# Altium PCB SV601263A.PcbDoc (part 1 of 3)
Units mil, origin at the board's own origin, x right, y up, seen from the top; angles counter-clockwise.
Board outline 4070 x 6530 mil, 6 copper layers (Top Layer, Signal Layer 1, Signal Layer 2, Signal Layer 3, Signal Layer 4, Bottom Layer), stack 60.36 mil thick; 305 components, 177 nets, 942 pads, 354 vias.
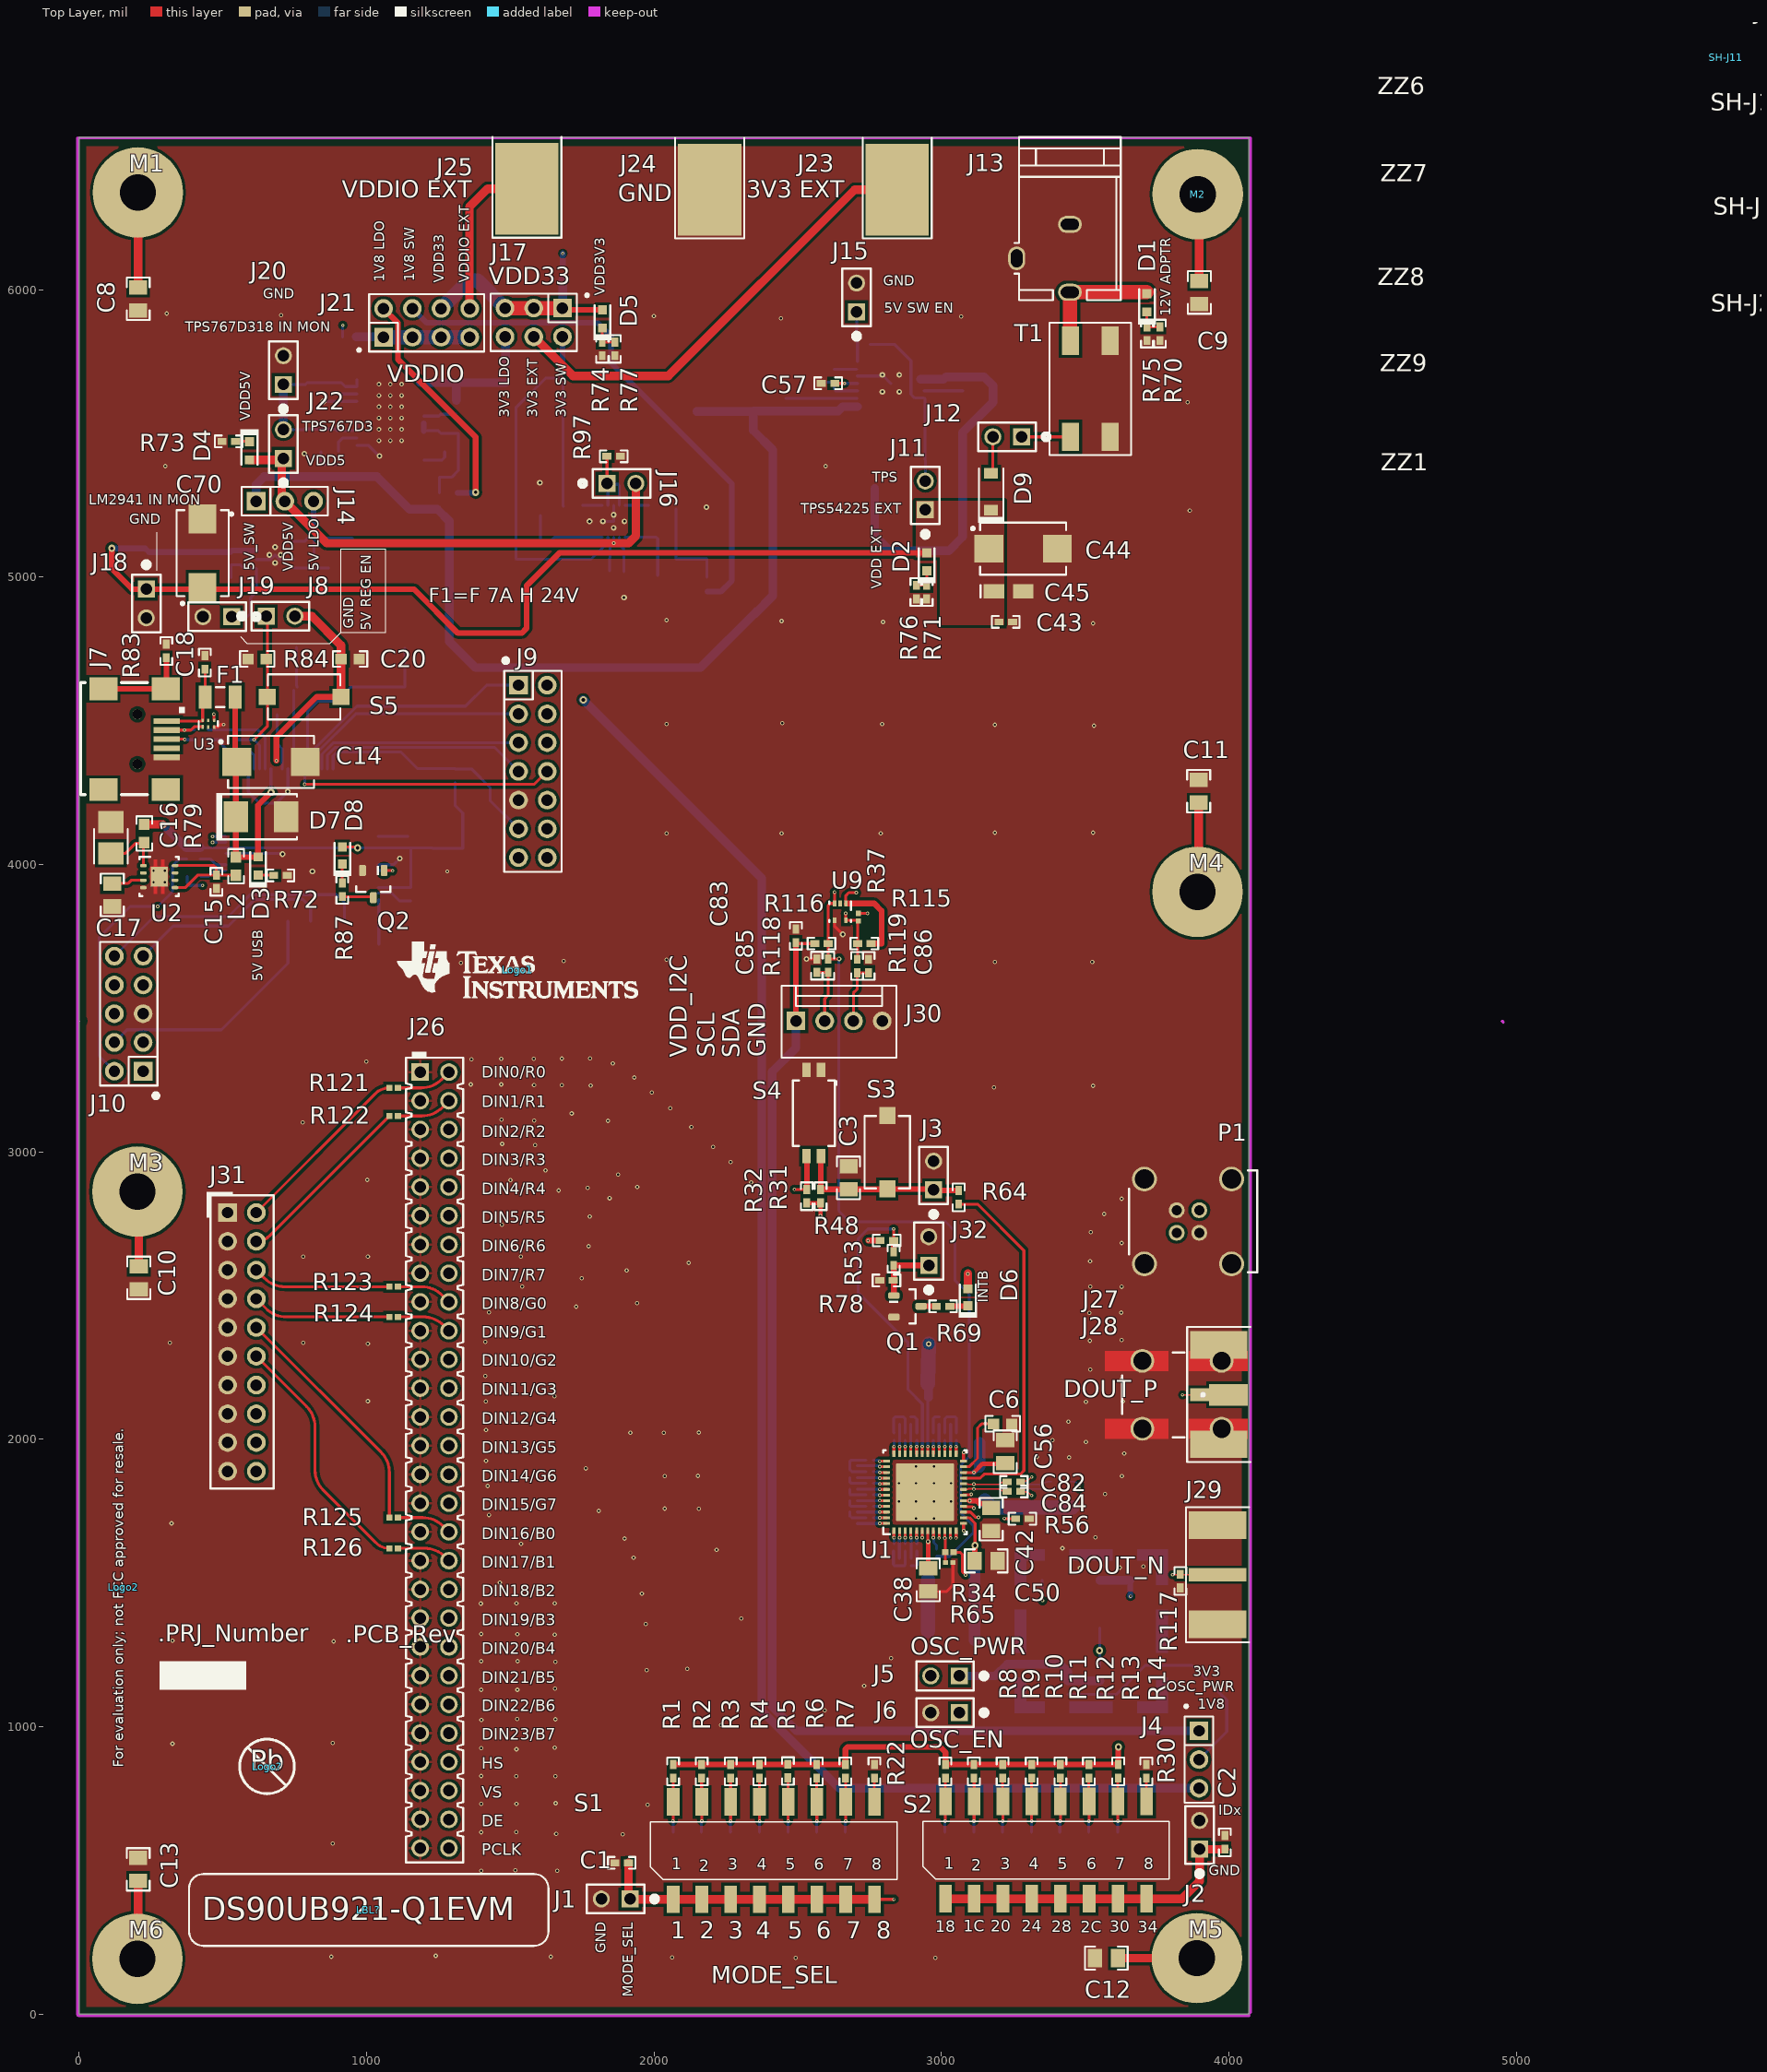
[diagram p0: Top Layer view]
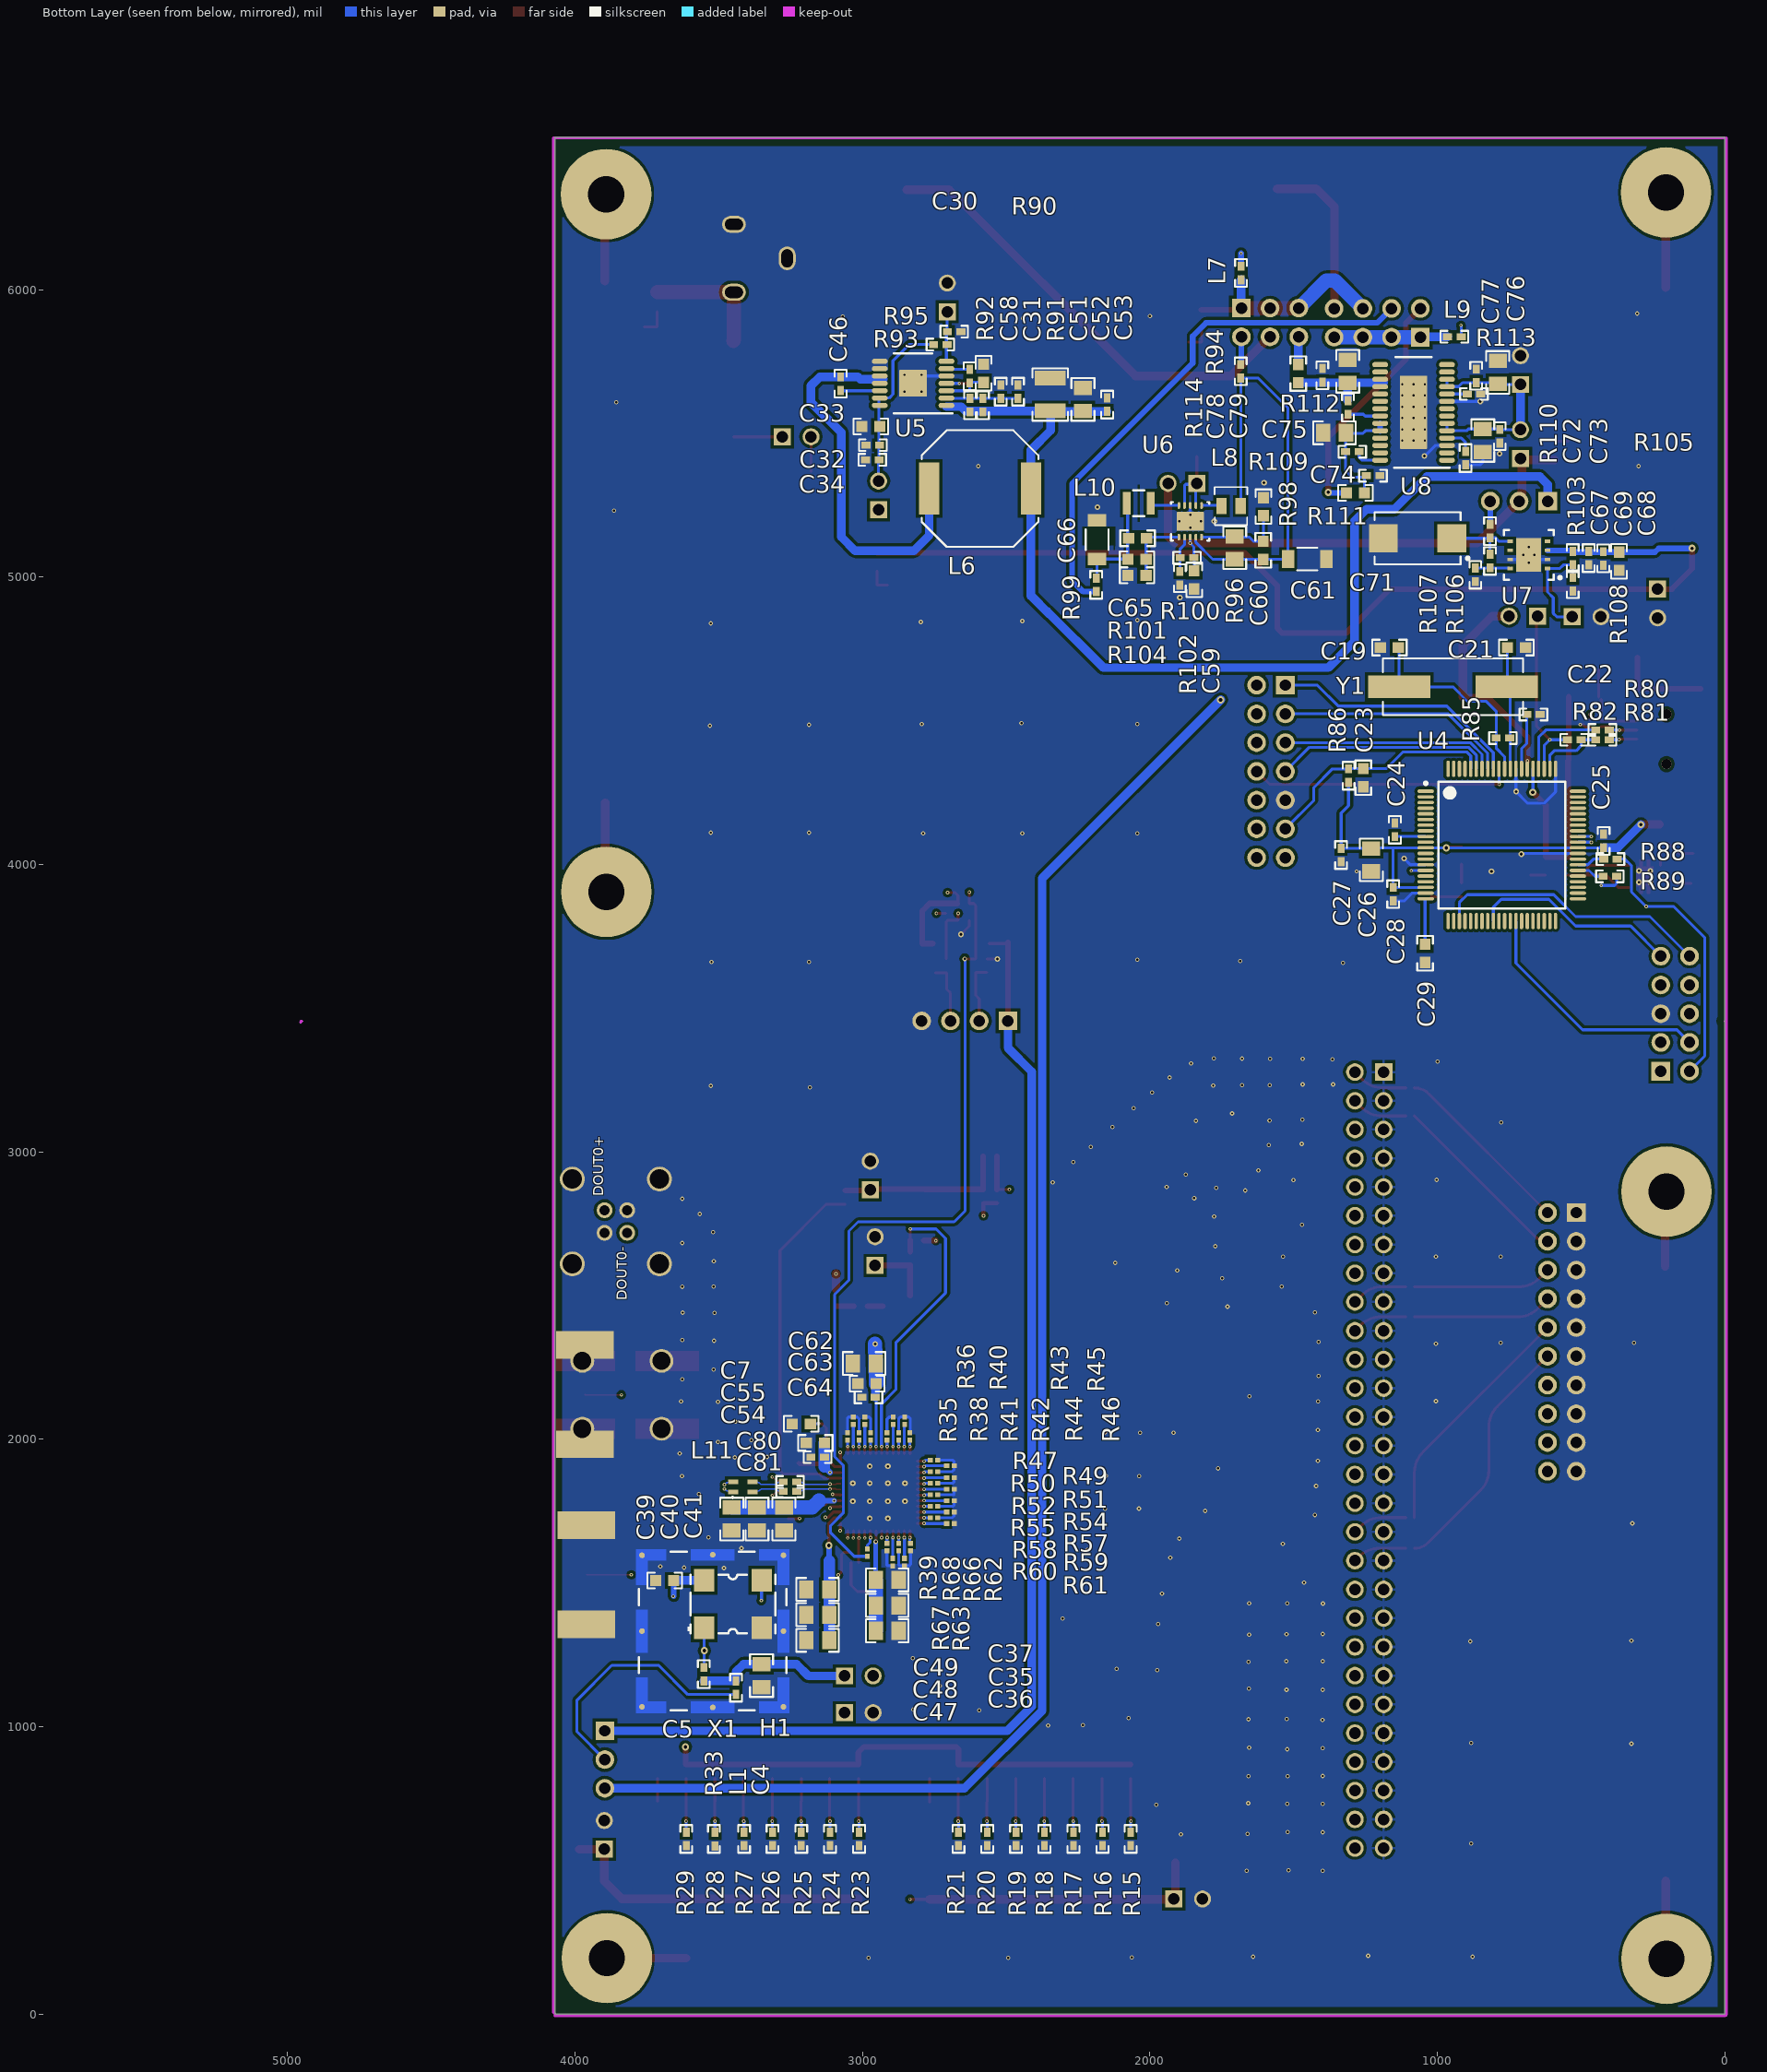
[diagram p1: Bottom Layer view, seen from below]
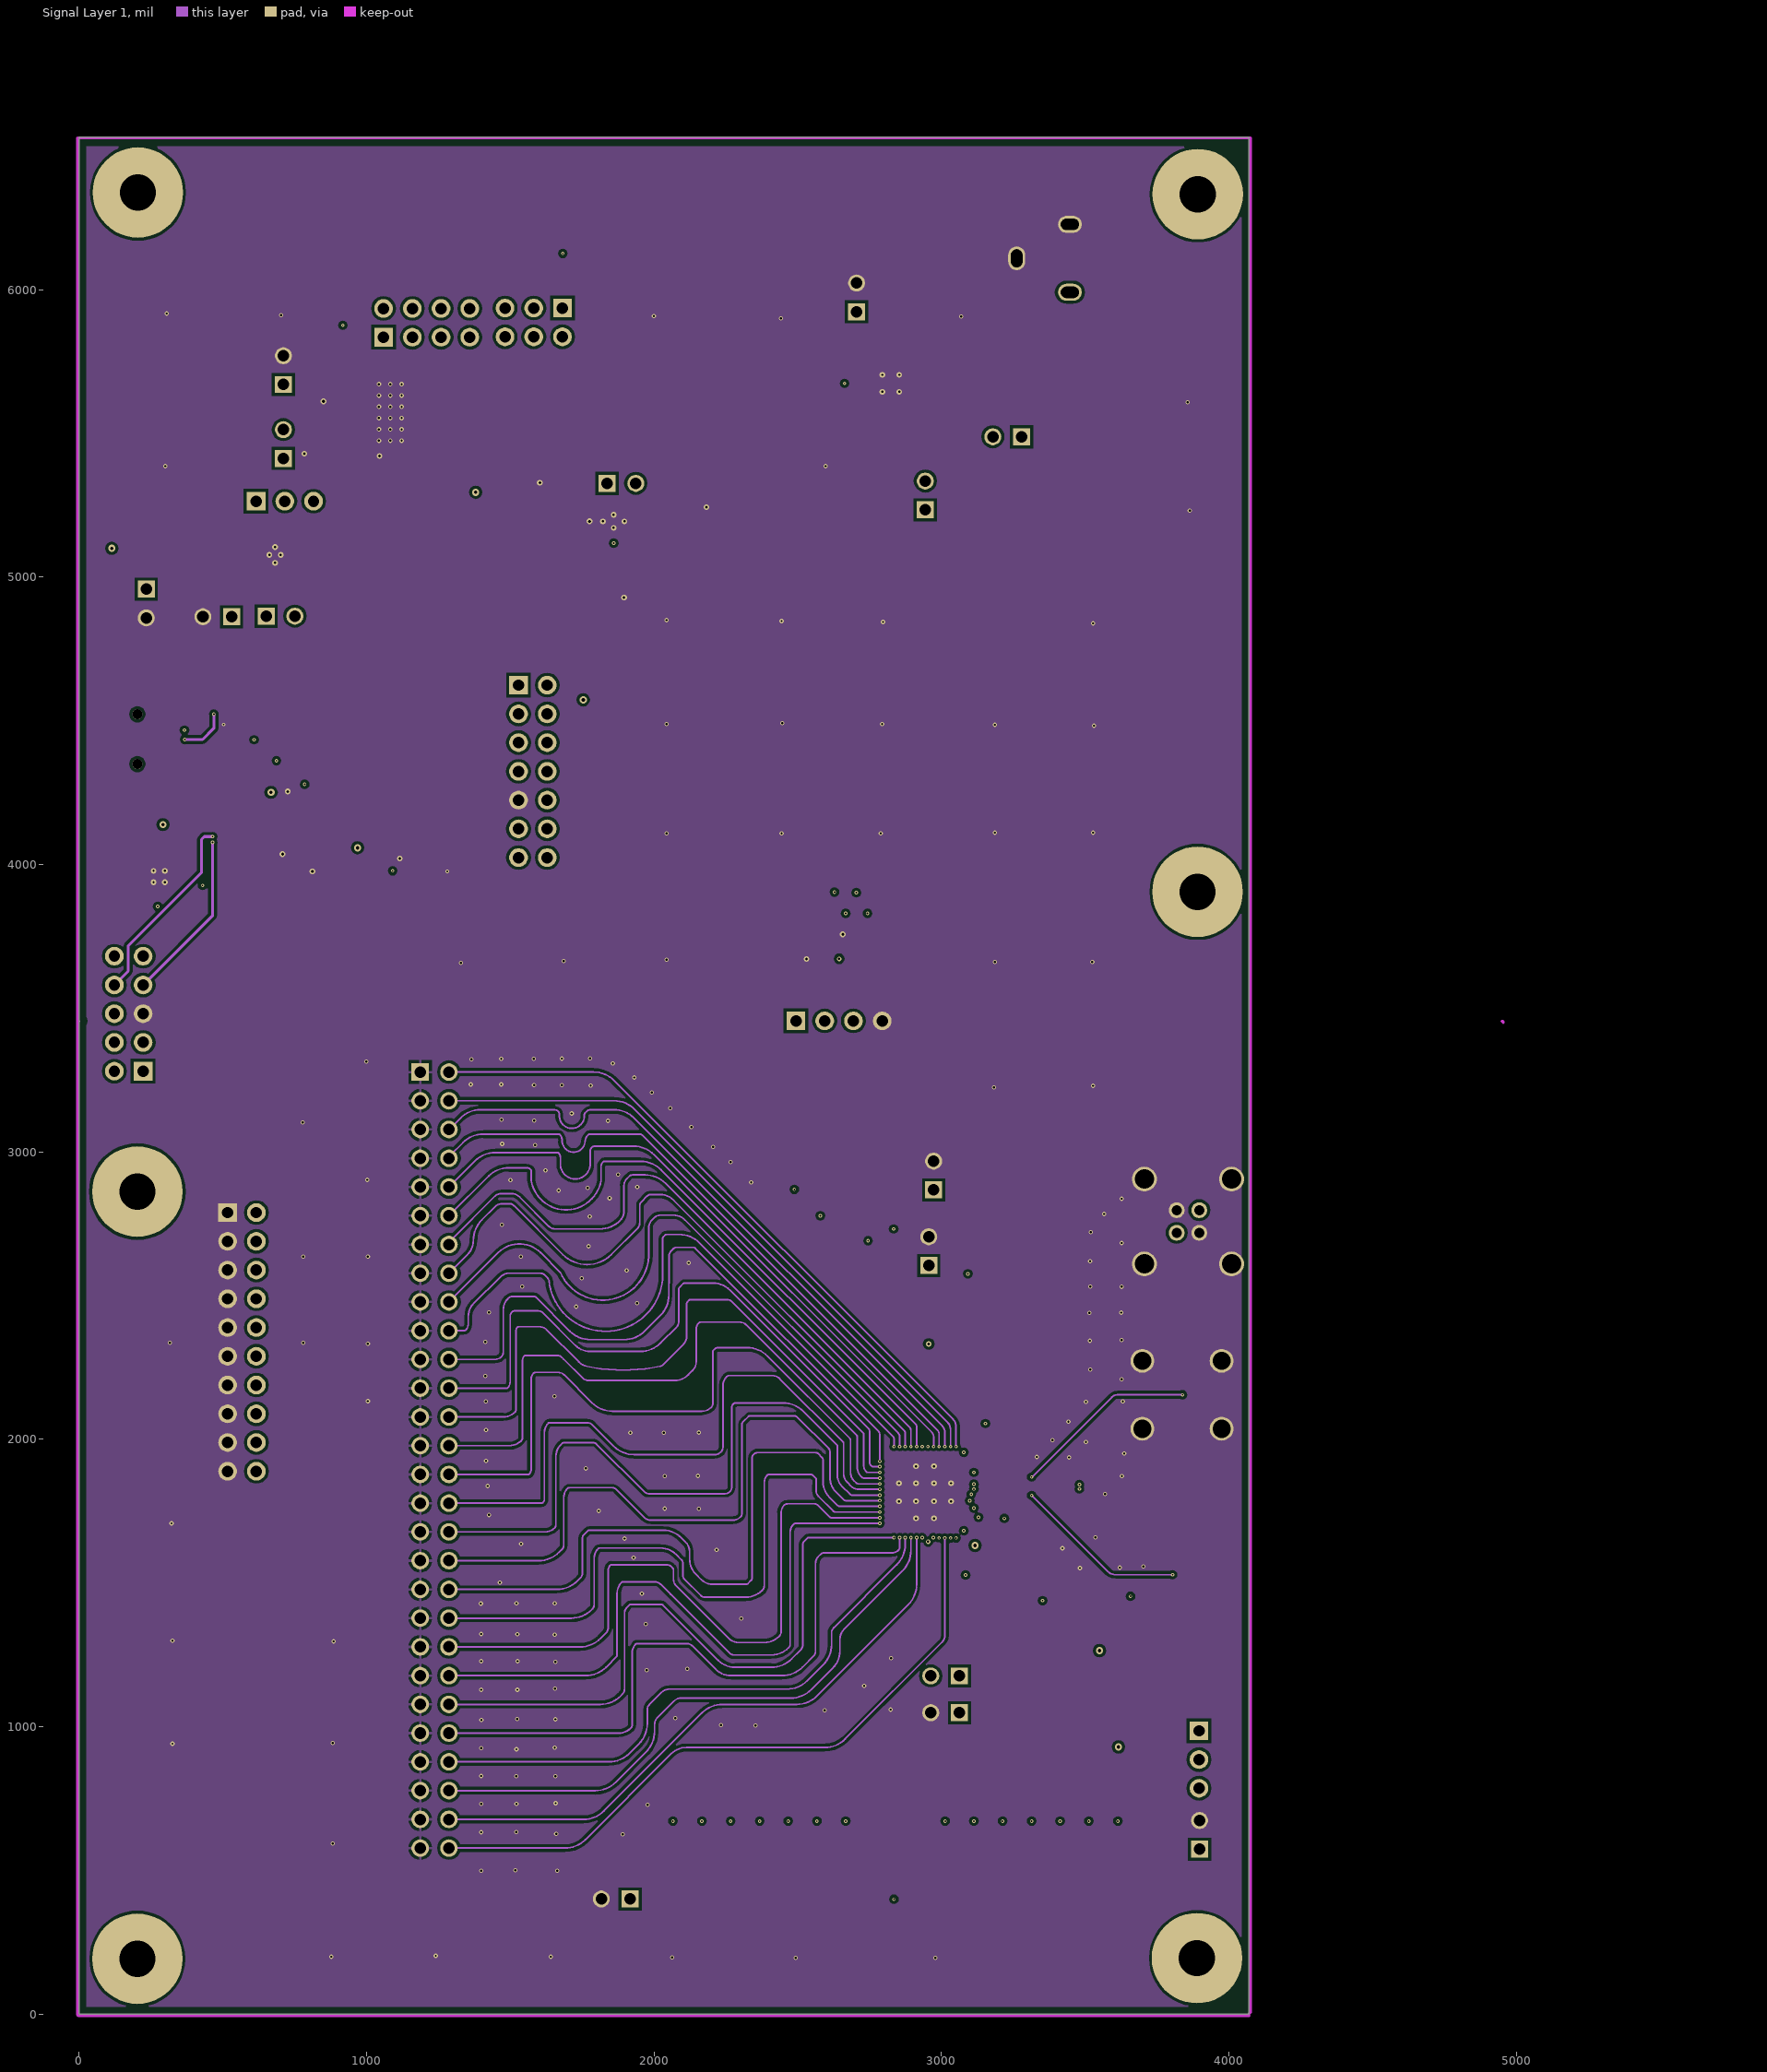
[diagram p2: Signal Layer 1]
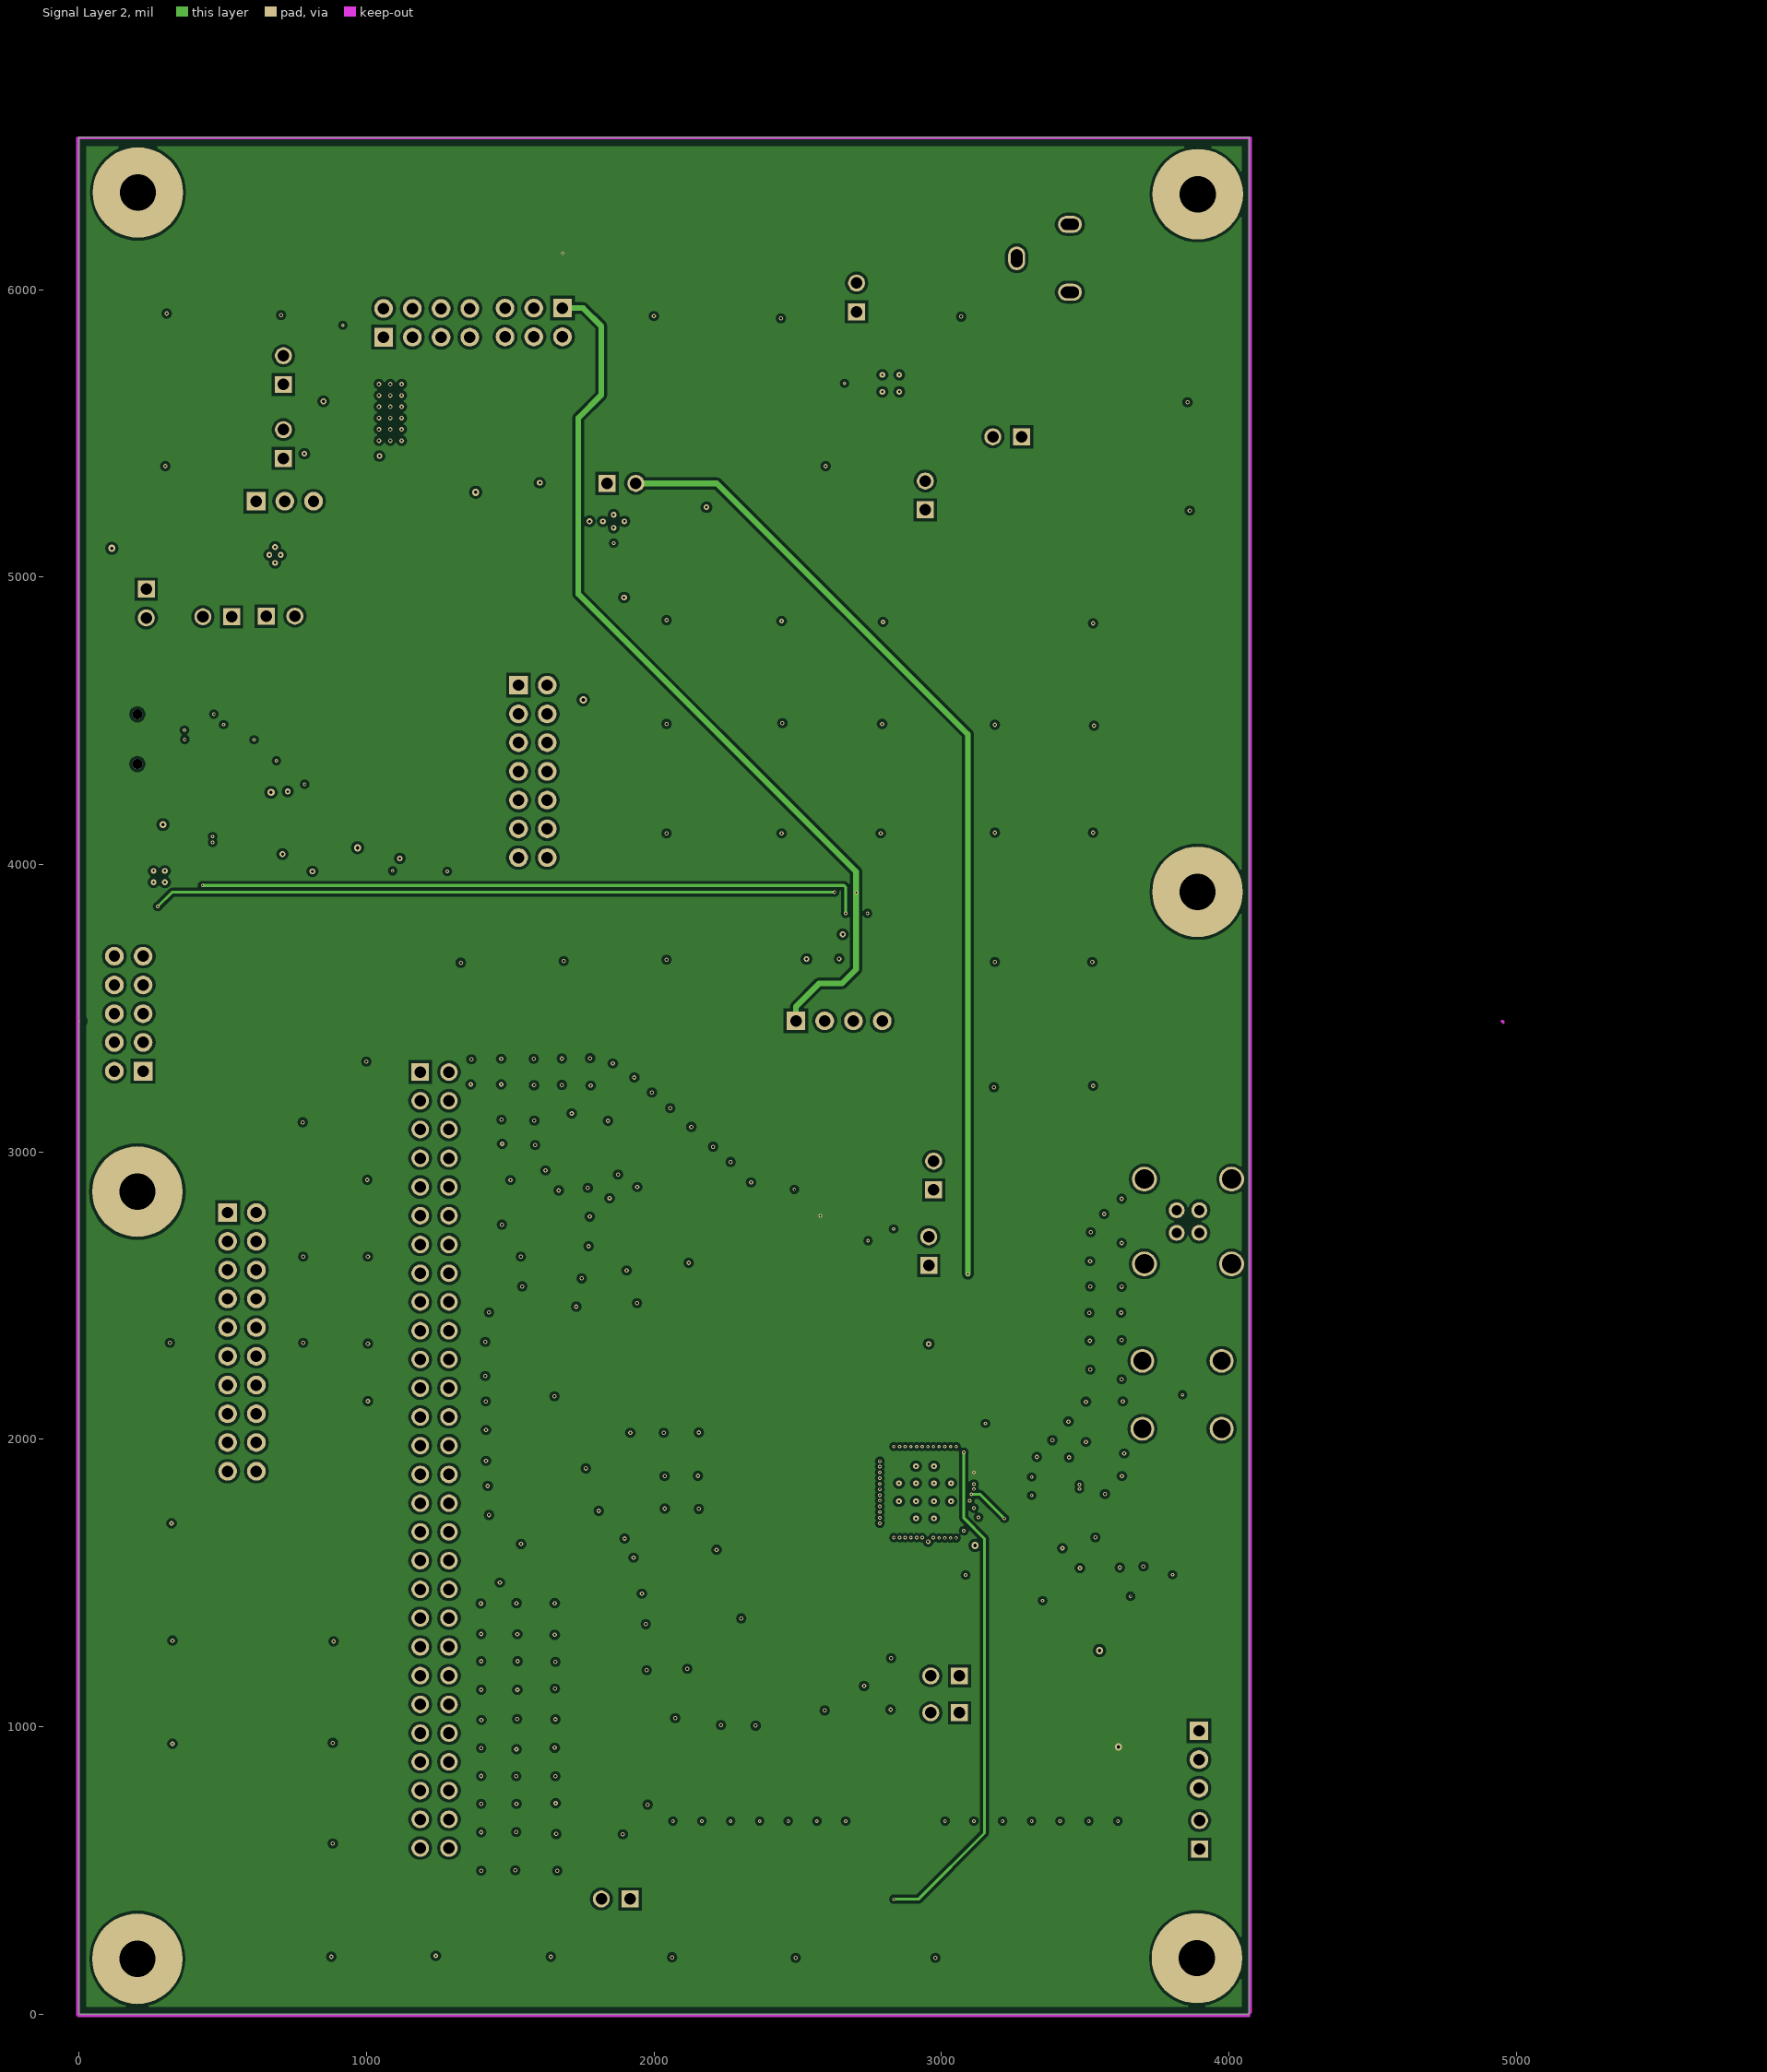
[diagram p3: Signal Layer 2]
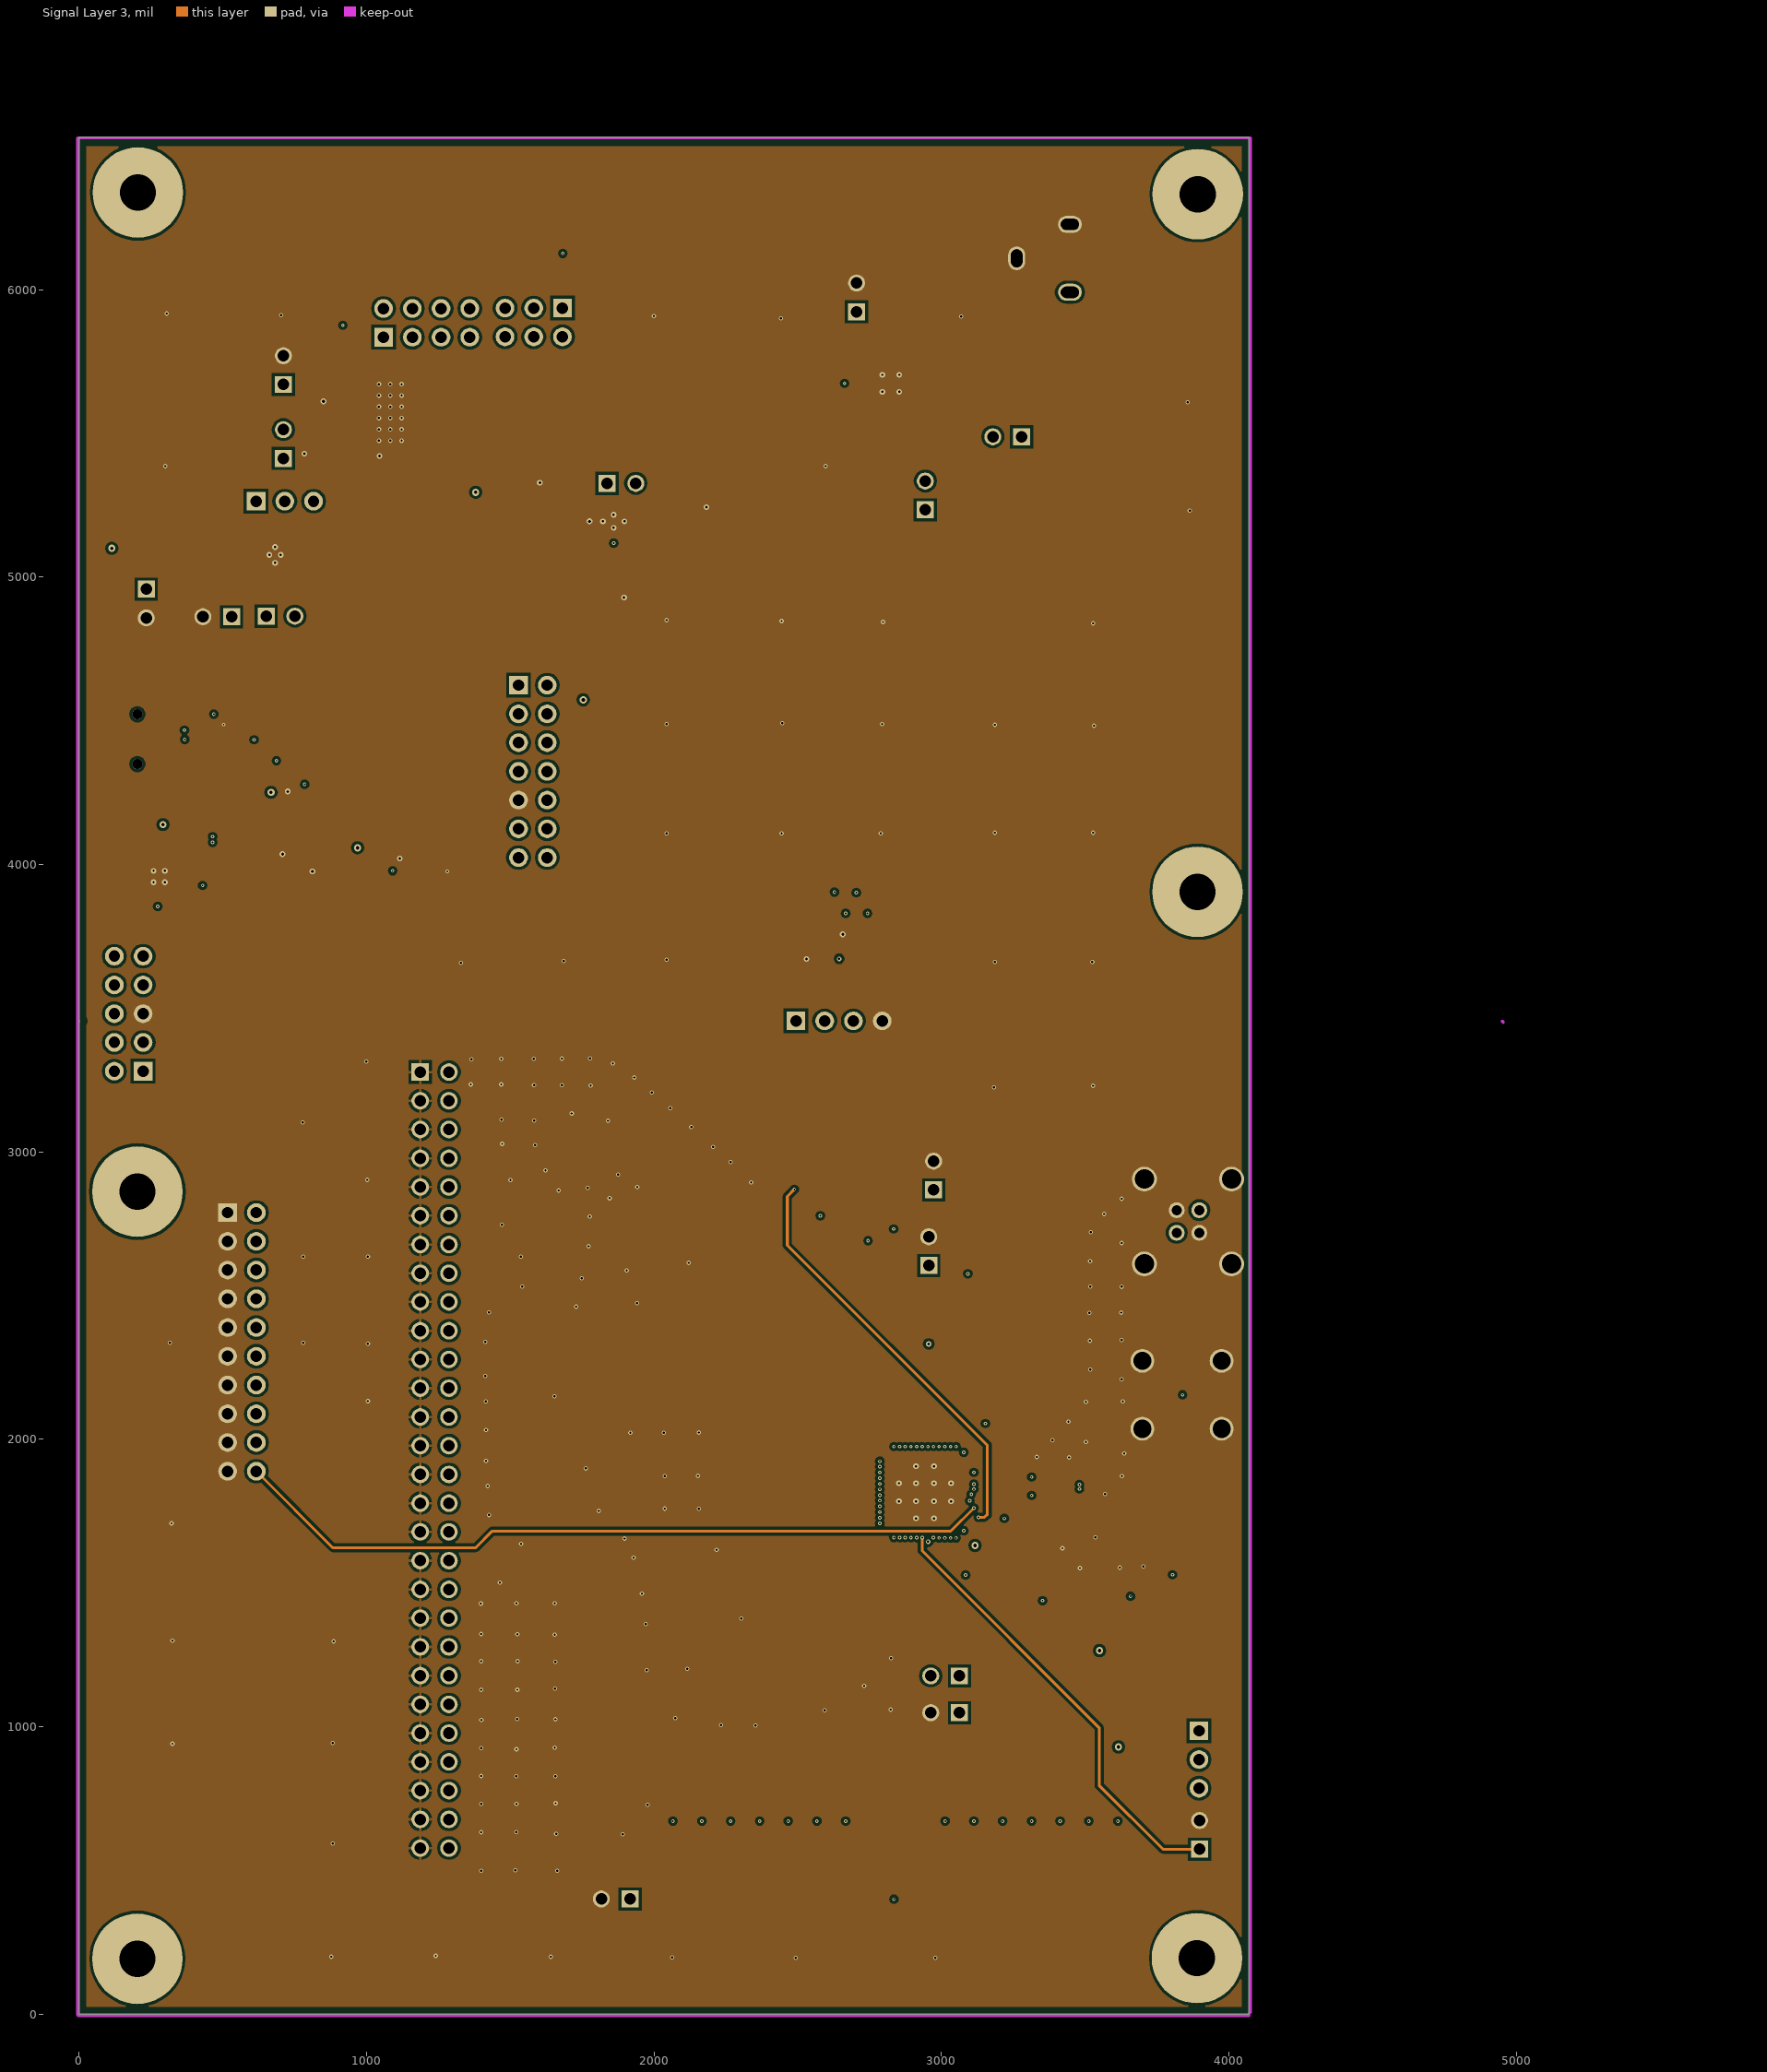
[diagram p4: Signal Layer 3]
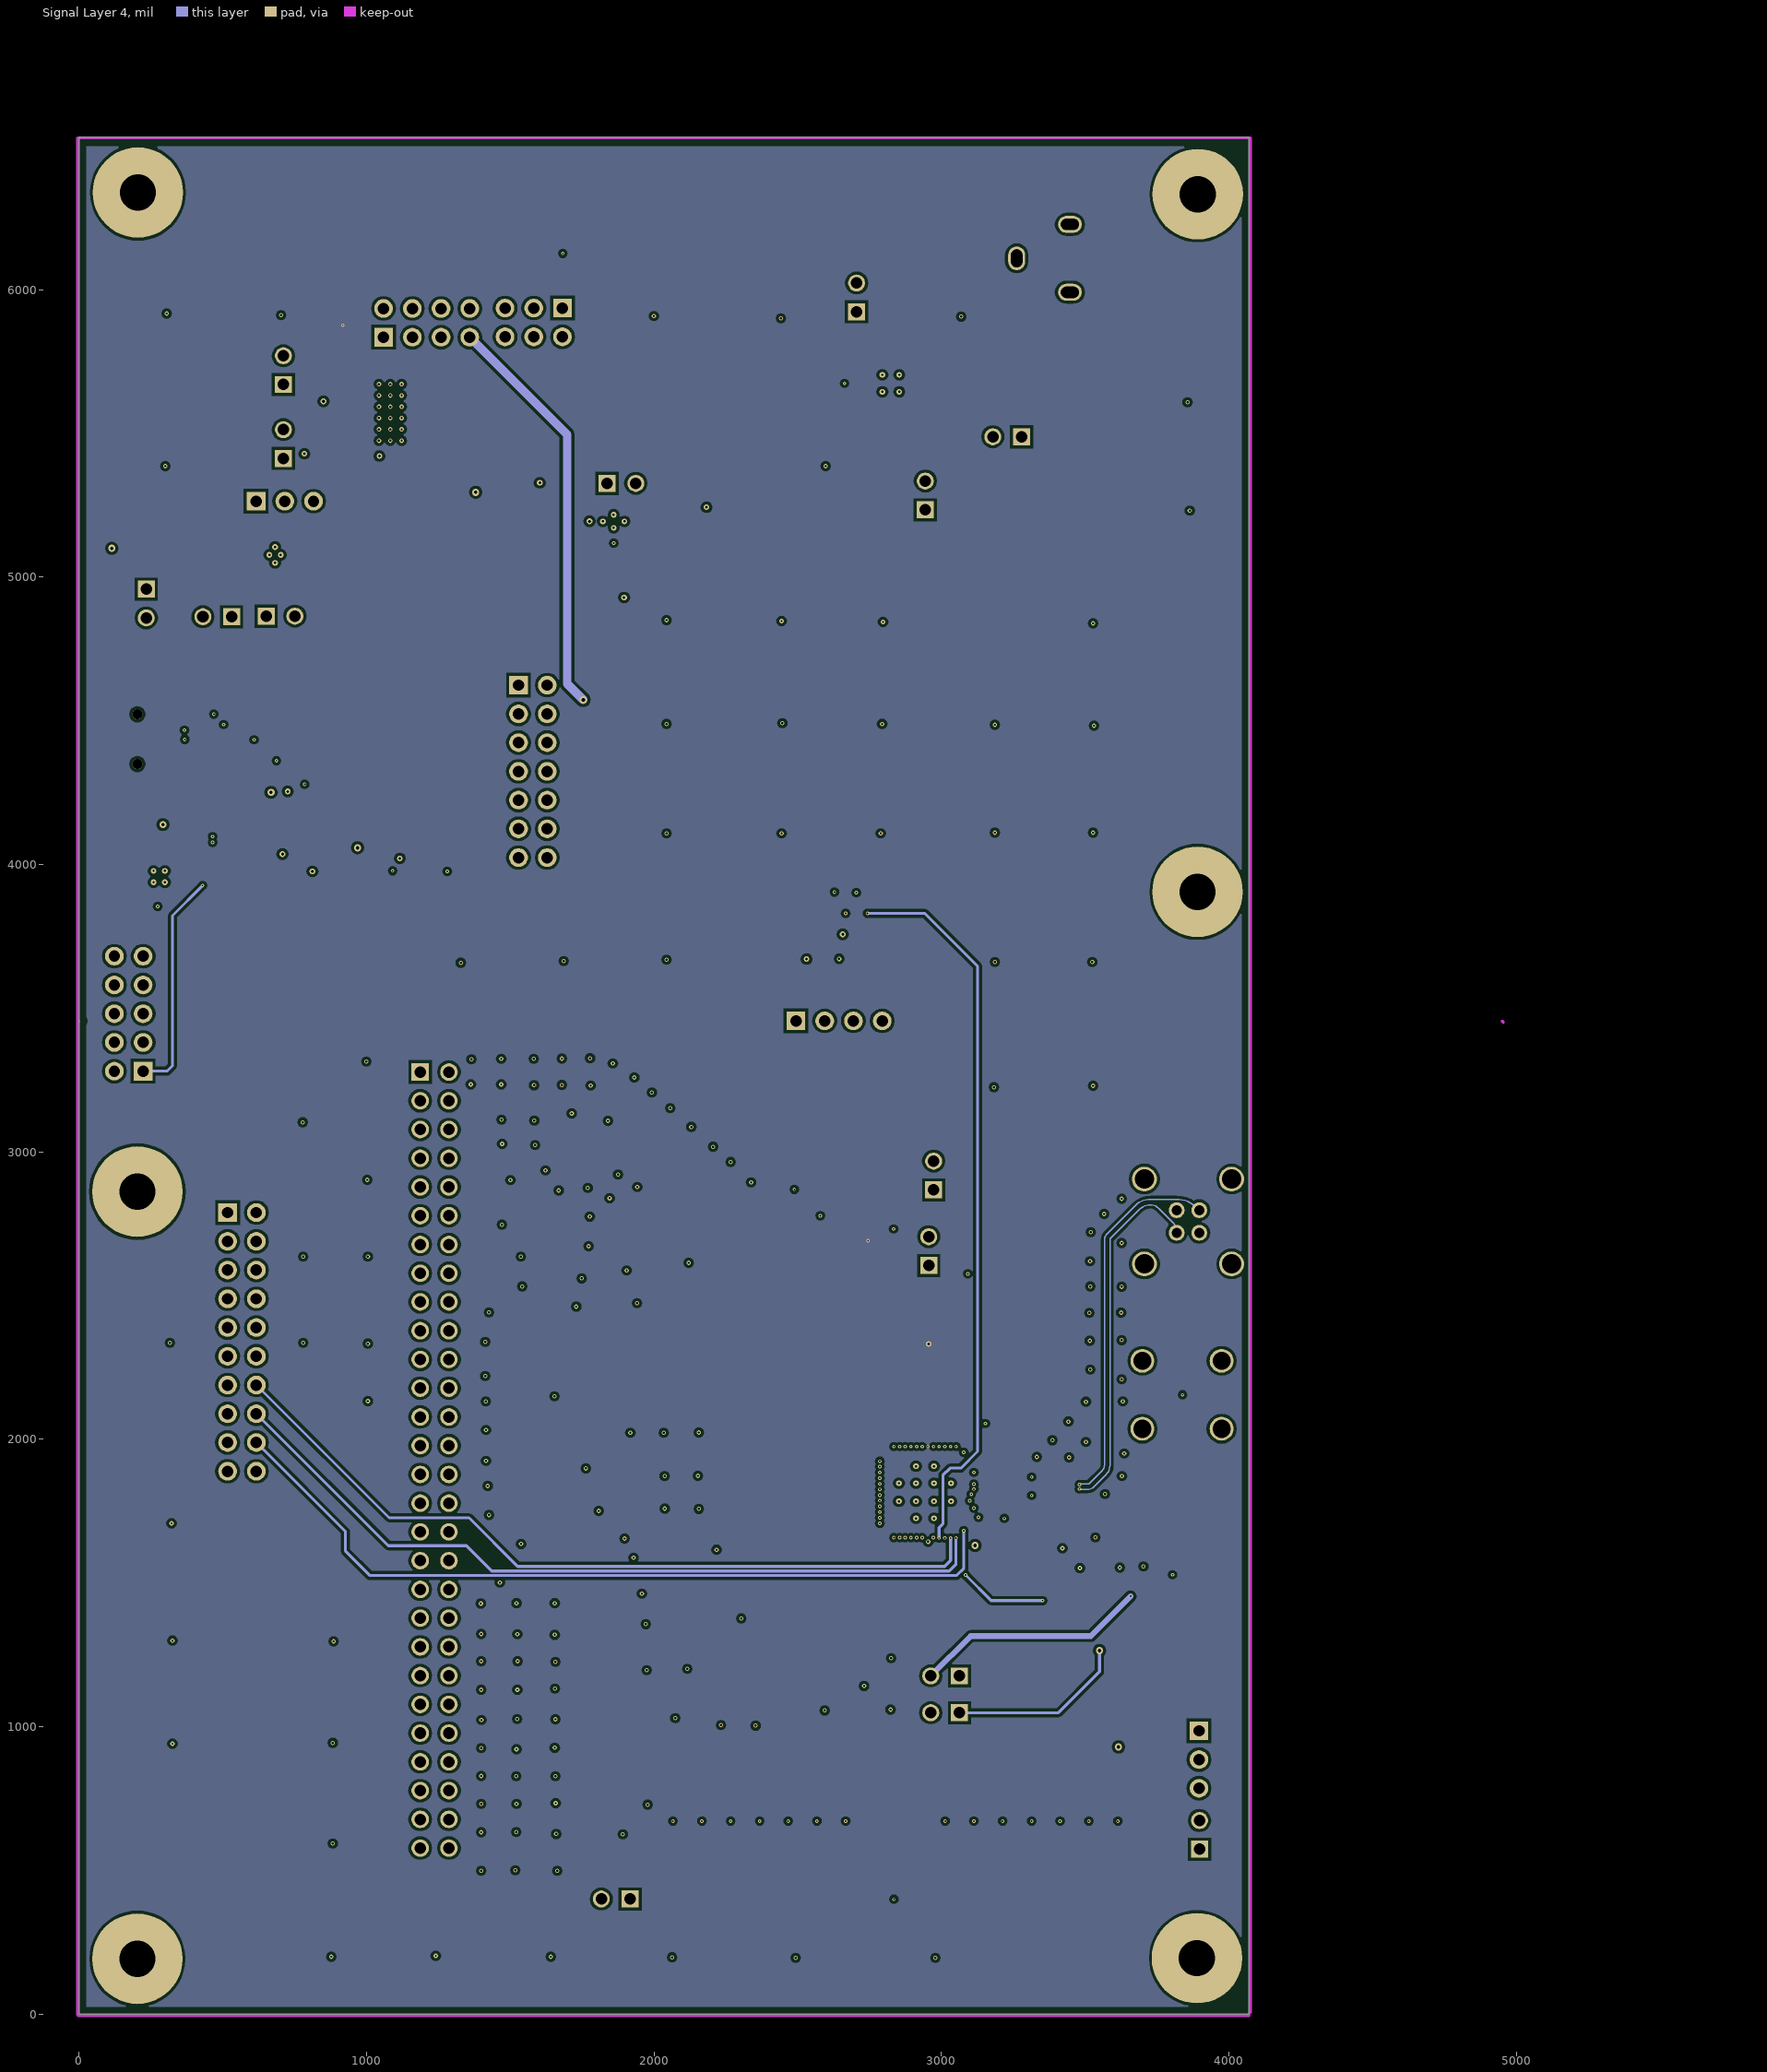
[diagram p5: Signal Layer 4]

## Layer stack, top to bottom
Top Solder: solder mask 0.7, Solder Resist, Dk 3.5
Top Layer: signal copper 1.58
Dielectric1: core 5, FR-4, Dk 4.2
Signal Layer 1: signal copper 1.3
Dielectric 3: prepreg 6, Dk 4.2
Signal Layer 2: signal copper 1.3
Dielectric 4: core 30, Dk 4.2
Signal Layer 3: signal copper 1.3
Dielectric 5: prepreg 6, Dk 4.2
Signal Layer 4: signal copper 1.3
Dielectric 2: core 5, Dk 4.2
Bottom Layer: signal copper 1.58
Bottom Solder: solder mask 0.7, Solder Resist, Dk 3.5

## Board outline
0,0 4070,0 4070,6530 0,6530

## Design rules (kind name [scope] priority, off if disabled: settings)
AcuteAngle [All] p1: minimum=4.50000000000000E+0001 checktracksonly=FALSE
AssemblyTestPointUsage [All] p1: valid=2
Clearance Clearance_Keepouts [((IsTrack Or IsArc) And Not InPoly) And IsFree and IsKeepOut vs ((IsTrack Or IsArc) And Not InPoly) And IsFree and IsKeepOut] p1: gap=0
Clearance Clearance_BoardEdge_MountingHoles [OnCopper and InComponentClass('Mounting Holes') vs IsKeepOut] p2: gap=40
Clearance Clearance_BoardEdge_Poly [OnCopper and InPoly vs IsKeepOut] p3: gap=25
Clearance Clearance_BoardEdge [OnCopper and Not InComponentClass('Logo') and not InComponentClass('FiducialMark') and not InRegion(1000,500,4000,800) and Not IsKeepout vs IsKeepOut] p4: gap=5
Clearance Clearance_Poly [InPolygon] p5: gap=10
Clearance [All] p6: gap=3.5
ComponentClearance ComponentClearance_MountingHoles_FiducialMarks [InComponentClass('Mounting Holes') vs InComponentClass('FiducialMark')] p1: gap=50 collisioncheckmode=3 verticalgap=10 showdistances=FALSE
ComponentClearance ComponentClearance_Shunt [InComponentClass('Header') vs InComponentClass('Shunt')] p2: gap=0 collisioncheckmode=3 verticalgap=0 showdistances=FALSE
ComponentClearance ComponentClearance_Logo [InComponentClass('Logo')] p3: gap=50 collisioncheckmode=3 verticalgap=10 showdistances=FALSE
ComponentClearance ComponentClearance_ScrewToNut [(HasFootprint('NY PMS 440 0025 PH')) vs (HasFootprint('Keystone_1902C'))] p4: gap=5 collisioncheckmode=3 verticalgap=10 showdistances=FALSE
ComponentClearance ComponentClearance_MountingHoles [InComponentClass('Mounting Holes')] p5: gap=10 collisioncheckmode=3 verticalgap=0 showdistances=FALSE
ComponentClearance ComponentClearance_SmallPassives [HasFootprint('0201*') or HasFootprint('0402*') or HasFootprint('0508') or HasFootprint('0603*') or HasFootprint('0612') or HasFootprint('0805*') or HasFootprint('0815*') or HasFootprint('0830*') or HasFootprint('1206*') or HasFootprint('1210*') or HasFootprint('1808*') or HasFootprint('1812*') or HasFootprint('1825*') or HasFootprint('2010*') or HasFootprint('2220*') or HasFootprint('2225*') or HasFootprint('2512*') or HasFootprint('2728*') or HasFootprint('3518*') vs HasFootprint('0201*') or HasFootprint('0402*') or HasFootprint('0508') or HasFootprint('0603*') or HasFootprint('0612') or HasFootprint('0805*') or HasFootprint('0815*') or HasFootprint('0830*') or HasFootprint('1206*') or HasFootprint('1210*') or HasFootprint('1808*') or HasFootprint('1812*') or HasFootprint('1825*') or HasFootprint('2010*') or HasFootprint('2220*') or HasFootprint('2225*') or HasFootprint('2512*') or HasFootprint('2728*') or HasFootprint('3518*')] p6: gap=5 collisioncheckmode=3 verticalgap=10 showdistances=FALSE
ComponentClearance ComponentClearance_THtoSMT [IsThruComponent vs IsSMTComponent] p7: gap=20 collisioncheckmode=3 verticalgap=30 showdistances=FALSE
ComponentClearance ComponentClearance_THtoTH [IsThruComponent vs IsThruComponent] p8: gap=10 collisioncheckmode=3 verticalgap=25 showdistances=FALSE
ComponentClearance [All] p9: gap=20 collisioncheckmode=3 verticalgap=10 showdistances=FALSE
DiffPairsRouting [All] p1: maxlimit=100 minlimit=10 mostfreqgap=15 toplayer_prefgap=10 toplayer_minwidth=5.5 toplayer_maxwidth=5.5 toplayer_prefwidth=5.5 midlayer1_mingap=15 midlayer1_minwidth=4.5 midlayer1_maxwidth=4.5 midlayer1_prefwidth=4.5 midlayer2_mingap=15 midlayer2_minwidth=4.5 midlayer2_maxwidth=4.5 midlayer2_prefwidth=4.5 midlayer3_mingap=15 midlayer3_minwidth=4.5 midlayer3_maxwidth=4.5 midlayer3_prefwidth=4.5 midlayer4_mingap=15 midlayer4_minwidth=4.5 midlayer4_maxwidth=4.5 midlayer4_prefwidth=4.5 bottomlayer_prefgap=10 bottomlayer_minwidth=5.5 bottomlayer_maxwidth=5.5 bottomlayer_prefwidth=5.5 maxuncoupledlength=1000
FabricationTestPointUsage TestPointUsage [All] p1: valid=2 allowmultiple=FALSE
FabricationTestpoint Testpoint [All] p1: side=3 testpointundercomponent=TRUE minsize=40 maxsize=100 preferedsize=60 minholesize=0 maxholesize=40 preferedholesize=32 testpointgrid=1 allowsidetop=TRUE allowsidebottom=TRUE usegrid=TRUE gridtolerance=0.01
FanoutControl Fanout_LCC [IsLCC] p1: bgadir=Out bgaviamode=Centered fanoutstyle=Auto fanoutdirection=Alternating viagrid=1 // Fanout_LCC (Default Rule)
FanoutControl Fanout_BGA [IsBGA] p2: bgadir=Out bgaviamode=Centered fanoutstyle=Auto fanoutdirection=Alternating viagrid=1 // Fanout_BGA (Default Rule)
FanoutControl Fanout_Default [All] p4: bgadir=Out bgaviamode=Centered fanoutstyle=Auto fanoutdirection=Alternating viagrid=1 // Fanout_Default (Default Rule)
FanoutControl Fanout_Small [(CompPinCount < 5)] p5: bgadir=Out bgaviamode=Centered fanoutstyle=Auto fanoutdirection=OutThenIn viagrid=1 // Fanout_Small (Default Rule)
HoleSize [All] p1: absolutevalues=TRUE maxlimit=251 minlimit=6 maxpercent=80.000 minpercent=20.000
HoleToHoleClearance [All] p1: gap=6 allowstackedmicrovias=TRUE
MinimumAnnularRing MinimumAnnularRing_ThermalPadVias [IsVia and InAnyComponent] p1: minimumring=3
MinimumAnnularRing [All] p2: minimumring=3
MinimumSolderMaskSliver MinimumSolderMaskSliver_Logo [InComponentClass('Logo') vs InComponentClass('Logo')] p1: minsoldermaskwidth=0.7
MinimumSolderMaskSliver [All] p2: minsoldermaskwidth=1
PlaneClearance [All] p1: clearance=10
PlaneConnect [All] p1: planeconnectstyle=Relief reliefexpansion=10 reliefentries=4 reliefconductorwidth=10 reliefairgap=10
PolygonConnect J26_relief_connect [InComponent('J26')] p1: connectstyle=Relief reliefconductorwidth=10 reliefentries=4 polygonreliefangle="90 Angle" airgapwidth=10
PolygonConnect [All] p2: connectstyle=Direct reliefconductorwidth=10 reliefentries=4 polygonreliefangle="90 Angle" airgapwidth=10
RoutingVias ThermalPadVias [IsVia and InAnyComponent] p1: holewidth=7.87 width=19.68 viastyle="Through Hole" minholewidth=6 minwidth=12 maxholewidth=12.99 maxwidth=23.62
RoutingVias [All] p2: holewidth=16 width=34 viastyle="Through Hole" minholewidth=6 minwidth=12 maxholewidth=40 maxwidth=65
SilkToBoardRegionClearance [Not ((IsComment or IsDesignator) And (Hide <> 'False')) and not InRegion(1000,500,4000,800)] p1:
SilkToSilkClearance SilkToSilkClearance_Pb-FreeLogo [(HasFootprint('Pb-Free_Overlay_Medium') OR HasFootprint('Pb-Free_Overlay_Small')) vs (HasFootprint('Pb-Free_Overlay_Medium') OR HasFootprint('Pb-Free_Overlay_Small'))] p1: silktosilkclearance=0
SilkToSilkClearance [All] p2: silktosilkclearance=0
SilkToSolderMaskClearance SilkToComonentPadClearance [IsPad and InAnycomponent] p1: minsilkscreentomaskgap=0 clearancetoexposedcopper=TRUE
SilkToSolderMaskClearance "Silk to Solder Mask Opening" [All] p2: minsilkscreentomaskgap=0 clearancetoexposedcopper=FALSE
SolderMaskExpansion [All] p1: expansion=1.97
Width [All] p1: maxlimit=100 minlimit=4 preferedwidth=10 minimp=50.000000 maximp=50.000000 favimp=50.000000 checkconnectedcopper=TRUE
13 further rules are at their usual default settings.

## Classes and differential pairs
component class Label: LBL?
component class Shunt: SH-J11 SH-J12 SH-J19 SH-J22
component class Header: J2 J4 J6 J9 J10 J11 J12 J14 J15 J16 J17 J19 J21 J22 J26 J31
component class SV601263A_Power: C6 C7 C30 C31 C32 C33 C34 C35 C36 C37 C38 C39 C40 C41 C42 C43 C44 C45 C46 C47 C48 C49 C50 C51 C52 C53 C54 C55 C56 C57 C58 C59 C60 C61 C62 C63 C64 C65 C66 C67 C68 C69 C70 C71 C72 C73 C74 C75 C76 C77 C78 C79 D9 J11 J12 J13 J14 J15 J16 J17 J18 J19 J20 J21 J22 J23 J24 J25 L6 L7 L8 L9 L10 R90 R91 R92 R93 R94 R95 R96 R97 R98 R99 R100 R101 R102 R103 R104 R105 R106 R107 R108 R109 R110 R111 R112 R113 R114 SH-J11 SH-J12 SH-J19 SH-J22 T1 U5 U6 U7 U8 ZZ6 ZZ7 ZZ8 ZZ9
component class SV601263A_MSP430F5529: C14 C15 C16 C17 C18 C19 C20 C21 C22 C23 C24 C25 C26 C27 C28 C29 D7 D8 F1 J7 J8 J9 J10 L2 Q2 R79 R80 R81 R82 R83 R84 R85 R86 R87 R88 R89 S5 U2 U3 U4 Y1
component class SV601263A_DS90UB921: C4 C5 J4 J5 J6 L1 R33 R34 R35 R36 R37 R38 R39 R40 R41 R42 R43 R44 R45 R46 R47 R48 R49 R50 R51 R52 R53 R54 R55 R56 R57 R58 R59 R60 R61 R62 R63 R64 R65 R66 R67 R68 U1 X1
component class SV601263A_CONNECTORS: C80 C81 C82 C83 C84 C85 C86 J26 J27 J28 J29 J30 J31 J32 L11 P1 R115 R116 R117 R118 R119 R121 R122 R123 R124 R125 R126 U9
component class SV601263A_CONFIG: C1 C2 C3 J1 J2 J3 R1 R2 R3 R4 R5 R6 R7 R8 R9 R10 R11 R12 R13 R14 R15 R16 R17 R18 R19 R20 R21 R22 R23 R24 R25 R26 R27 R28 R29 R30 R31 R32 S1 S2 S3 S4
component class AssemblyNote: ZZ1 ZZ2 ZZ3 ZZ4 ZZ5
component class SV601263A_LED: C8 C9 C10 C11 C12 C13 D1 D2 D3 D4 D5 D6 H1 LBL? Logo1 Logo2 Logo? M1 M2 M3 M4 M5 M6 Q1 R69 R70 R71 R72 R73 R74 R75 R76 R77 R78 ZZ1 ZZ2 ZZ3 ZZ4 ZZ5
component class Logo: Logo1
differential pair DOUT: +DOUT_P -DOUT_N
differential pair L10: +L10_P -L10_N
differential pair DOUTSMA0: +DOUTSMA0_P -DOUTSMA0_N
differential pair DOUT0SMA: +DOUT0SMA_P -DOUT0SMA_N

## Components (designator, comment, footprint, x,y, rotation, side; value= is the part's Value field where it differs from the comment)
C1 "GRM155R71C104KA88D" 0402#1 1888,527 r180 top
C2 "GRM155R71C104KA88D" 0402#1 3986,598 r90 top
C3 "GRM21BR71A106KE51L" 0805_HV 2677,2910 r90 top
C4 "GRM21BR71C475KA73L" 0805_HV 3351,1178 r270 bottom
C5 "06031C103JAT2A" 0603 3688,1509 r0 bottom
C6 "DNP" 0603 3213,2054 r0 top
C7 "GRM188R61C104KA01D" 0603 3213,2054 r0 bottom
C8 "08051C472KAT2A" 0805_HV 206,5968 r270 top
C9 "08051C472KAT2A" 0805_HV 3897,5990 r270 top
C10 "08051C472KAT2A" 0805_HV 208,2562 r270 top
C11 "08051C472KAT2A" 0805_HV 3895,4255 r90 top
C12 "08051C472KAT2A" 0805_HV 3574,195 r180 top
C13 "08051C472KAT2A" 0805_HV 206,504 r90 top
C14 "293D226X0020D2TE3" 7343-31 668,4357 r0 top
C15 "C1005X5R0J105M050BB" 0402#1 478,3940 r270 top
C16 "293D225X9025B2TE3" 3528-21 111,4093 r90 top
C17 "08051C103KAT2A" 0805_HV 116,3894 r270 top
C18 "GRM155R71C104KA88D" 0402#1 438,4703 r270 top
C19 "GRM1885C2A200JA01D" 0603 1167,4755 r180 bottom
C20 "06035A221FAT2A" 0603 943,4715 r180 top
C21 "GRM1885C2A200JA01D" 0603 725,4755 r0 bottom
C22 "GRM1555C1H201JA01D" 0402#1 666,4522 r180 bottom
C23 "C0603X222K5RACTU" 0603 1258,4302 r90 bottom
C24 "GRM155R71C104KA88D" 0402#1 1148,4121 r90 bottom
C25 "GRM155R71C104KA88D" 0402#1 422,4082 r90 bottom
C26 "GRM21BR71A106KE51L" 0805_HV 1230,4016 r270 bottom
C27 "GRM155R71C104KA88D" 0402#1 1335,4033 r90 bottom
C28 "GRM155R71C104KA88D" 0402#1 1154,3897 r270 bottom
C29 "GRM188R71C474KA88D" 0603 1043,3691 r270 bottom
C30 "GRM1555C1H100JA01D" 0402#1 2581,5598 r270 bottom
C31 "GRM1555C1H100JA01D" 0402#1 2519,5645 r270 bottom
C32 "GRM155R71C104KA88D" 0402#1 2964,5459 r0 bottom
C33 "C1608X7R1C105K" 0603 2971,5524 r0 bottom
C34 "GRM155R71C104KA88D" 0402#1 2966,5408 r0 bottom
C35 "GCM21BR71C475KA73L" 0805_HV 2914,1422 r180 bottom
C36 "GCM21BR71C475KA73L" 0805_HV 2914,1334 r180 bottom
C37 "GCM21BR71C475KA73L" 0805_HV 2914,1511 r180 bottom
C38 "GCM21BR71C475KA73L" 0805_HV 2954,1511 r270 top
C39 "GCM21BR71C475KA73L" 0805_HV 3455,1723 r270 bottom
C40 "GCM21BR71C475KA73L" 0805_HV 3367,1723 r270 bottom
C41 "GCM21BR71C475KA73L" 0805_HV 3273,1723 r270 bottom
C42 "GCM21BR71C475KA73L" 0805_HV 3173,1722 r270 top
C43 "GRM155R71C104KA88D" 0402#1 3224,4844 r180 top
C44 "293D226X0025D2TE3" 7343-31 3284,5099 r0 top
C45 "293D225X9025A2TE3" 3216-18 3234,4951 r0 top
C46 "GRM155R71C104KA88D" 0402#1 3076,5673 r90 bottom
C47 "GCM21BR71C475KA73L" 0805_HV 3156,1301 r0 bottom
C48 "GCM21BR71C475KA73L" 0805_HV 3156,1390 r0 bottom
C49 "GCM21BR71C475KA73L" 0805_HV 3156,1478 r0 bottom
C50 "GCM21BR71C475KA73L" 0805_HV 3156,1577 r0 top
C51 "GRM32ER61C476ME15L" 1210 2347,5635 r90 bottom
C52 "GRM21BR71A106KE51L" 0805_HV 2233,5618 r90 bottom
C53 "GRM155R71C104KA88D" 0402#1 2149,5600 r270 bottom
C54 "GRM155R71C473KA01D" 0402#1 3156,1938 r0 bottom
C55 "GRM188R71E474KA12D" 0603 3164,1988 r0 bottom
C56 "GCM21BR71C475KA73L" 0805_HV 3222,1957 r90 top
C57 "GRM155R71H332KA01D" 0402#1 2606,5674 r180 top
C58 "C1608X7R1C105K" 0603 2579,5709 r90 bottom
C59 "GRM188R61E106MA73D" 0603 1846,4990 r90 bottom
C60 "DNP" 0603 1606,5093 r90 bottom
C61 "C3216X5R1V226M160AC" 1206_190 1453,5063 r180 bottom
C62 "GCM21BR71C475KA73L" 0805_HV 2994,2264 r0 bottom
C63 "GRM188R71E474KA12D" 0603 2984,2194 r0 bottom
C64 "GRM155R71C473KA01D" 0402#1 2979,2146 r0 bottom
C65 "06035A330JAT2A" 0603 2043,5135 r180 bottom
C66 "C3216X5R1V226M160AC" 1206_190 2184,5130 r90 bottom
C67 "C1005X7R1H104K" 0402#1 474,5066 r270 bottom
C68 "GRM188R61E106MA73D" 0603 368,5055 r270 bottom
C69 "GRM155R61C474KE01" 0402#1 423,5065 r270 bottom
C70 "293D226X0025D2TE3" 7343-31 430,5083 r90 top
C71 "293D226X0025D2TE3" 7343-31 1069,5135 r0 bottom
C72 "GRM21BR71C475KA73L" 0805_HV 842,5475 r90 bottom
C73 "GRM155R71C104KA88D" 0402#1 783,5490 r270 bottom
C74 "GRM155R71C104KA88D" 0402#1 1224,5353 r0 bottom
C75 "GRM21BR71A106KE51L" 0805_HV 1358,5502 r0 bottom
C76 "GRM21BR71C475KA73L" 0805_HV 790,5712 r270 bottom
C77 "GRM155R71C104KA88D" 0402#1 865,5700 r90 bottom
C78 "GRM155R71C104KA88D" 0402#1 1400,5702 r270 bottom
C79 "GRM21BR71A106KE51L" 0805_HV 1312,5716 r90 bottom
C80 "DNP" 0402#1 3252,1852 r180 bottom
C81 "DNP" 0402#1 3252,1819 r180 bottom
C82 "C1005X5R1A334K050BB" 0402#1 3252,1852 r180 top
C83 "GRM155R71C104KA88D" 0402#1 2494,3752 r270 top
C84 "C1005X5R1A154K050BC" 0402#1 3252,1819 r180 top
C85 "GRM1555C1E4R7CA01D" 0402#1 2567,3648 r90 top
C86 "GRM1555C1E4R7CA01D" 0402#1 2747,3647 r90 top
D1 "150060VS75000" WL-SMCW_GREEN 3715,5954 r90 top
D2 "150060VS75000" WL-SMCW_GREEN 2949,5053 r90 top
D3 "150060VS75000" WL-SMCW_GREEN 623,3995 r90 top
D4 "150060VS75000" WL-SMCW_GREEN 593,5439 r270 top
D5 "150060VS75000" WL-SMCW_GREEN 1821,5898 r90 top
D6 "LTST-C190KFKT" LED_LTST-C190 3092,2494 r270 top
D7 "1SMB5922BT3G" SMB 633,4166 r0 top
D8 "LTST-C190GKT" LED_LTST-C190 916,4031 r270 top
D9 "1N5819HW-7-F" SOD-123 3173,5297 r90 top
F1 "0429007.WRML" FUSE_429 491,4583 r180 top
H1 "BMI-S-201-F" Laird_BMI-S-201-F 3521,1333 r180 bottom
J1 "5-146261-1" CONN_5-146261-1 1867,401 r180 top
J2 "5-146261-1" CONN_5-146261-1 3898,624 r90 top
J3 "5-146261-1" CONN_5-146261-1 2973,2918 r90 top
J4 "TSW-103-07-G-S" TSW-103-07-G-S 3896,886 r270 top
J5 "5-146261-1" CONN_5-146261-1 3013,1177 r180 top
J6 "5-146261-1" CONN_5-146261-1 3013,1049 r180 top
J7 "1734035-2" CONN_USB-Mini-B-1734035-2 203,4436 r270 top
J8 "5-146261-1" CONN_5-146261-1 701,4864 r0 top
J9 "PEC07DAAN" CONN_PEC07DAAN 1579,4324 r270 top
J10 "PEC05DAAN" CONN_PEC05DAAN 173,3481 r90 top
J11 "5-146261-1" CONN_5-146261-1 2944,5284 r90 top
J12 "5-146261-1" CONN_5-146261-1 3229,5488 r180 top
J13 "PJ-102A" CONN_PJ-102A 3447,6109 r90 top
J14 "TSW-103-07-G-S" TSW-103-07-G-S 716,5264 r0 top
J15 "5-146261-1" CONN_5-146261-1 2705,5973 r90 top
J16 "5-146261-1" CONN_5-146261-1 1887,5326 r0 top
J17 "TSW-103-07-G-D" TSW-103-07-G-D 1582,5886 r180 top
J18 "5-146261-1" CONN_5-146261-1 234,4908 r270 top
J19 "5-146261-1" CONN_5-146261-1 481,4862 r180 top
J20 "5-146261-1" CONN_5-146261-1 711,5720 r90 top
J21 "TSW-104-07-G-D" TSW-104-07-G-D 1209.52,5884.48 r0 top
J22 "5-146261-1" CONN_5-146261-1 711,5463 r90 top
J23 "6091" 6091 2846,6533 r270 top
J24 "6092" 6092 2194,6533 r270 top
J25 "6091" 6091 1558,6536 r270 top
J26 "TSW-128-07-G-D" Samtec_TSW-128-07-G-D 1237,1928 r270 top
J27 "59S20X-40ML5-Z" Rosenberger_59S20X-40ML5-Z 4079,2155 r270 top
J28 "142-0701-851" Emerson_142-0701-851 4075,2156 r270 top
J29 "142-0701-851" Emerson_142-0701-851 4071,1529 r270 top
J30 "0022112042" CONN_22112042 2644,3456 r0 top
J31 "PEC10DAAN" SULLINS_PEC10DAAN 567,2339 r0 top
J32 "5-146261-1" CONN_5-146261-1 2956,2655 r90 top
L1 "BLM15AX102SN1D" 0402#1 3440,1136 r270 bottom
L2 "BK1608HS600-T" 0603 546,3994 r270 top
L6 "7440650047" WE-TPC-XLH2 2591,5308 r0 bottom
L7 "BLM15AX102SN1D" 0402#1 1683,6058 r90 bottom
L8 "VLF302510MT-2R2M" VLF302510MT 1718,5247 r180 bottom
L9 "BLM15AX102SN1D" 0402#1 941,5836 r180 bottom
L10 "MLP2520S3R3ST0S1" MLP2520S-S 2039,5257 r0 bottom
L11 "DLW21SN900HQ2L" IND_DLW21S 3416,1835 r90 bottom
LBL? "Size: 1.25\" x 0.25\"" Label_1250x250 1008,363 r0 top
Logo1 "Texas Instruments" TI_Stacked_Overlay_Small 1526,3633 r0 top
Logo2 "FCC disclaimer" FCC_disclaimer 154,1486 r90 top
Logo? "Pb-Free Symbol" Pb-Free_Overlay_Medium 654,862 r0 top
M1 "TESTPOINT" TESTPOINT 205,6338 r0 top
M2 "TESTPOINT" TESTPOINT 3892,6332 r0 top
M3 "TESTPOINT" TESTPOINT 203,2862 r0 top
M4 "TESTPOINT" TESTPOINT 3891,3905 r0 top
M5 "TESTPOINT" TESTPOINT 3889,195 r0 top
M6 "TESTPOINT" TESTPOINT 203,193 r0 top
P1 "D4S20D-40ML5-Z" Rosenberger_D4S20L-40MA5_NoTopLayerPads 4106,2758 r90 top
Q1 "BSS138" SOT-23 2882,2463 r0 top
Q2 "BSS138" SOT-23 1024,3932 r270 top
R1 "ERJ-2GE0R00X" 0402#1 2067,845 r90 top
R2 "CRCW0402107KFKED" 0402#1 2166,845 r90 top
R3 "CRCW0402255KFKED" 0402#1 2267,845 r90 top
R4 "ERJ-2RKF1003X" 0402#1 2367,845 r90 top
R5 "CRCW0402105KFKED" 0402#1 2466,846 r90 top
R6 "CRCW0402102KFKED" 0402#1 2566,845 r90 top
R7 "CRCW040217K8FKED" 0402#1 2666,845 r90 top
R8 "ERJ-2GE0R00X" 0402#1 3014,845 r90 top
R9 "CRCW0402107KFKED" 0402#1 3113,845 r90 top
R10 "CRCW0402255KFKED" 0402#1 3213,845 r90 top
R11 "ERJ-2RKF1003X" 0402#1 3314,845 r90 top
R12 "CRCW0402105KFKED" 0402#1 3414,845 r90 top
R13 "CRCW0402102KFKED" 0402#1 3513,845 r90 top
R14 "CRCW040217K8FKED" 0402#1 3615,845 r90 top
R15 "CRCW040210K0FKED" 0402#1 2067,610 r90 bottom
R16 "CRCW040217K8FKED" 0402#1 2165,610 r90 bottom
R17 "CRCW0402102KFKED" 0402#1 2266,610 r90 bottom
R18 "CRCW040275K0JNED" 0402#1 2367,610 r90 bottom
R19 "CRCW0402140KFKED" 0402#1 2466,610 r90 bottom
R20 "CRCW0402255KFKED" 0402#1 2566,610 r90 bottom
R21 "CRCW0402107KFKED" 0402#1 2666,610 r90 bottom
R22 "ERJ-2GE0R00X" 0402#1 2767,845 r270 top
R23 "CRCW040210K0FKED" 0402#1 3012,610 r90 bottom
R24 "CRCW040217K8FKED" 0402#1 3113,610 r90 bottom
R25 "CRCW0402102KFKED" 0402#1 3213,610 r90 bottom
R26 "CRCW040275K0JNED" 0402#1 3313,610 r90 bottom
R27 "CRCW0402140KFKED" 0402#1 3412,610 r90 bottom
R28 "CRCW0402255KFKED" 0402#2 3517,610 r90 bottom
R29 "CRCW0402107KFKED" 0402#1 3613,610 r90 bottom
R30 "ERJ-2GE0R00X" 0402#1 3713,845 r270 top
R31 "CRCW040210K0FKED" 0402#1 2580,2846 r270 top
R32 "CRCW040210K0FKED" 0402#1 2532,2846 r270 top
R33 "CRCW040210K0FKED" 0402#1 3552,1183 r270 bottom
R34 "ERJ-1GE0R00C" 0201M 3028,1607 r180 top
R35 "ERJ-1GEF49R9C" 0201 3052,2010 r270 bottom
R36 "ERJ-1GEF49R9C" 0201 3032,2065 r90 bottom
R37 "ERJ-1GE0R00C" 0201 2711,3817 r270 top
R38 "ERJ-1GEF49R9C" 0201 3012,2010 r90 bottom
R39 "ERJ-1GE0R00C" 0201 2983,1606 r270 bottom
R40 "ERJ-1GEF49R9C" 0201 2992,2065 r90 bottom
R41 "ERJ-1GEF49R9C" 0201 2972,2010 r90 bottom
R42 "ERJ-1GEF49R9C" 0201 2915,2010 r90 bottom
R43 "ERJ-1GEF49R9C" 0201 2893,2065 r90 bottom
R44 "ERJ-1GEF49R9C" 0201 2874,2010 r90 bottom
R45 "ERJ-1GEF49R9C" 0201 2853,2065 r90 bottom
R46 "ERJ-1GEF49R9C" 0201 2835,2010 r90 bottom
R47 "ERJ-1GEF49R9C" 0201 2751,1928 r180 bottom
R48 "CRCW04024K70JNED" 0402#1 2810,2692 r180 top
R49 "ERJ-1GEF49R9C" 0201 2694,1908 r180 bottom
R50 "ERJ-1GEF49R9C" 0201 2751,1888 r180 bottom
R51 "ERJ-1GEF49R9C" 0201 2694,1867 r180 bottom
R52 "ERJ-1GEF49R9C" 0201 2751,1847 r180 bottom
R53 "ERJ-2GE0R00X" 0402#1 2834,2629 r270 top
R54 "ERJ-1GEF49R9C" 0201 2694,1827 r180 bottom
R55 "ERJ-1GEF49R9C" 0201 2751,1807 r180 bottom
R56 "ERJ-2GE0R00X" 0402#1 3282,1724 r0 top
R57 "ERJ-1GEF49R9C" 0201 2694,1787 r180 bottom
R58 "ERJ-1GEF49R9C" 0201 2751,1767 r180 bottom
R59 "ERJ-1GEF49R9C" 0201 2694,1747 r180 bottom
R60 "ERJ-1GEF49R9C" 0201 2751,1727 r180 bottom
R61 "ERJ-1GEF49R9C" 0201 2694,1707 r180 bottom
R62 "ERJ-1GEF49R9C" 0201 2833,1625 r270 bottom
R63 "ERJ-1GEF49R9C" 0201 2854,1573 r270 bottom
R64 "ERJ-2GE0R00X" 0402#1 3060,2842 r90 top
R65 "ERJ-1GEF49R9C" 0201 3027,1571 r0 top
R66 "ERJ-1GEF49R9C" 0201 2874,1625 r270 bottom
R67 "ERJ-1GEF49R9C" 0201 2895,1573 r270 bottom
R68 "ERJ-1GEF49R9C" 0201 2915,1625 r270 bottom
R69 "CRCW0402470RJNED" 0402#1 3006,2463 r0 top
R70 "CRCW04022K40JNED" 0402#1 3760,5847 r90 top
R71 "CRCW04022K40JNED" 0402#1 2949,4948 r90 top
R72 "CRCW0402220RJNED" 0402#1 701,3962 r180 top
R73 "CRCW0402220RJNED" 0402#1 521,5472 r0 top
R74 "CRCW0402180RJNED" 0402#1 1820,5794 r90 top
R75 "CRCW04022K40JNED" 0402#1 3715,5847 r90 top
R76 "CRCW04022K40JNED" 0402#1 2913,4948 r90 top
R77 "CRCW0402180RJNED" 0402#1 1864,5794 r90 top
R78 "CRCW0402100KJNED" 0402#1 2809,2553 r0 top
R79 "CRCW06030000Z0EA" 0603 227,4108 r90 top
R80 "CRCW040233R0JNED" 0402#1 426,4468 r180 bottom
R81 "CRCW040233R0JNED" 0402#1 426,4434 r180 bottom
R82 "CRCW04021K50JNED" 0402#1 524,4434 r180 bottom
R83 "CRCW040233K0JNED" 0402#1 304,4743 r270 top
R84 "CRCW06031M20JNEA" 0603 620,4715 r0 top
R85 "DNP" 0402#1 772,4440 r0 bottom
R86 "CRCW040233K0JNED" 0402#1 1309,4309 r90 bottom
R87 "CRCW0402200RJNED" 0402#1 916,3912 r90 top
R88 "RC0402JR-070RL" 0402#1 398,4019 r0 bottom
R89 "RC0402JR-070RL" 0402#1 400,3959 r180 bottom
R90 "CRCW0402124KFKED" 0402#1 2626,5598 r90 bottom
R91 "CRCW040222K1FKED" 0402#1 2459,5645 r90 bottom
R92 "CRCW0402100KJNED" 0402#1 2627,5699 r270 bottom
R93 "CRCW040210K0FKED" 0402#1 2729,5809 r180 bottom
R94 "ERJ-2GE0R00X" 0402#1 1684,5716 r90 bottom
R95 "CRCW04023K24FKED" 0402#1 2681,5854 r0 bottom
R96 "RT0805BRD07806KL" 0805_HV 1705,5102 r90 bottom
R97 "CRCW040210K0FKED" 0402#1 1860,5420 r180 top
R98 "RG1608P-184-B-T5" 0603 1605,5245 r270 bottom
R99 "ERJ-2GE0R00X" 0402#1 2187,4973 r270 bottom
R100 "CRCW040210K0FKED" 0402#1 1871,5067 r180 bottom
R101 "RT0603BRD07361KL" 0603 2045,5062 r180 bottom
R102 "DNP" 0402#1 1896,4996 r90 bottom
R103 "CRCW040210K0FKED" 0402#1 529,5066 r90 bottom
R104 "RG1608P-184-B-T5" 0603 2045,5006 r180 bottom
R105 "ERJ-2GE0R00X" 0402#1 817,5160 r90 bottom
R106 "CRCW040229K4FKED" 0402#1 817,5056 r90 bottom
R107 "CRCW040210K0FKED" 0402#1 868,5008 r90 bottom
R108 "CRCW04023K24FKED" 0402#1 529,4975 r90 bottom
R109 "CRCW0402100KJNED" 0402#1 1296,5436 r180 bottom
R110 "ERJ-2GE0R00X" 0402#1 902,5414 r90 bottom
R111 "CRCW06030000Z0EA" 0603 1285,5293 r0 bottom
R112 "CRCW0402100KJNED" 0402#1 1311,5590 r90 bottom
R113 "ERJ-2GE0R00X" 0402#1 873,5637 r0 bottom
R114 "CRCW06030000Z0EA" 0603 1484,5708 r90 bottom
R115 "CRCW04024K70JNED" 0402#1 2732,3725 r0 top
R116 "CRCW04024K70JNED" 0402#1 2583,3725 r180 top
R117 "CRCW040249R9FKED" 0402#1 3831,1507 r90 top
R118 "ERJ-2GE0R00X" 0402#1 2606,3648 r270 top
R119 "ERJ-2GE0R00X" 0402#1 2707,3647 r270 top
R121 "ERJ-1GE0R00C" 0201M 1095,3223 r0 top
R122 "ERJ-1GE0R00C" 0201M 1095,3125 r0 top
R123 "ERJ-1GE0R00C" 0201M 1095,2531 r0 top
R124 "ERJ-1GE0R00C" 0201M 1095,2426 r0 top
R125 "ERJ-1GE0R00C" 0201M 1095,1728 r0 top
R126 "ERJ-1GE0R00C" 0201M 1095,1621 r0 top
S1 "219-8MST" SW_219-8MST 2417,569 r90 top
S2 "219-8MST" SW_219-8MST 3364,571 r90 top
S3 "KSR221GLFS" KSR 2812,2999 r90 top
S4 "218-2LPST" SW_218-2LP 2556,3135 r270 top
S5 "KSR221GLFS" KSR 783,4583 r0 top
SH-J11 "969102-0000-DA" SNT-100-BK-G 5730,6808 r90 top
SH-J12 "969102-0000-DA" SNT-100-BK-G 5718,6491 r90 top
SH-J19 "969102-0000-DA" SNT-100-BK-G 5727,6128 r90 top
SH-J22 "969102-0000-DA" SNT-100-BK-G 5719,5792 r90 top
T1 "ACM9070-701-2PL" ACM9070 3518,5655 r270 top
U1 "DS90UB921TRHSRQ1" RHS0048A 2943,1816 r90 top
U2 "TPS73533DRBT" DRB0008A 279,3958 r0 top
U3 "TPD4E004DRYR" DRY0006A 450,4490 r90 top
U4 "MSP430F5529IPN" PN0080A_N 776,4068 r180 bottom
U5 "TPS54225PWPR" PWP0014E_N 2824,5674 r0 bottom
U6 "TPS62410QDRCRQ1" DRC0010J 1860,5194 r90 bottom
U7 "LM2941LD/NOPB" LDC08A 682,5077 r0 bottom
U8 "TPS767D318PWP" PWP0028D_N 1083,5573 r0 bottom
U9 "TPD2E001DRLR" DRL0005A 2648,3835 r270 top
X1 "FXO-HC736R-96" FOX_FXO-HC73 3451,1427 r90 bottom
Y1 "ECS-240-20-5PX-TR" XTAL_CSM-7X 946,4618 r0 bottom
ZZ1 "Place H1 over X1" AssemblyNote 4674,5487 r0 top
ZZ2 "This Assembly Note is for PCB labels only" AssemblyNoteLabel 78,7832 r0 top
ZZ3 "These assemblies are ESD sensitive, ESD precautions shall be observed" AssemblyNoteLabel 73,7646 r0 top
ZZ4 "These assemblies must be clean and free from flux and all contaminants. Use of no clean flux is not acceptable" AssemblyNoteLabel 124,7481 r0 top
ZZ5 "These assemblies must comply with workmanship standards IPC-A-610 Class 2., unless otherwise specified" AssemblyNoteLabel 143,7311 r0 top
ZZ6 "Place Jumper on J12" AssemblyNote 4680,6805 r0 top
ZZ7 "Place Jumper on J11" AssemblyNote 4695,6502 r0 top
ZZ8 "Place Jumper on J19" AssemblyNote 4674,6130 r0 top
ZZ9 "Place Jumper on J22" AssemblyNote 4674,5827 r0 top

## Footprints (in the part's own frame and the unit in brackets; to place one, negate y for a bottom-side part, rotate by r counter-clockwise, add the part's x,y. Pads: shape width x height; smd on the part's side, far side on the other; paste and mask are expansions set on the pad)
0201 [mm] "Data from Kemet datasheet CC101_COM dated 7/28/11"
  rect 0.46x0.42 smd mask+0.048: 1(-0.33,0) 2(0.33,0)
  body extent -0.31,-0.16 0.31,0.16, height 0.26
0201M [mm] "Data from Kemet datasheet CC101_COM dated 7/28/11"
  rect 0.56x0.52 smd mask+0.048: 1(-0.38,0) 2(0.38,0)
  body extent -0.31,-0.16 0.31,0.16, height 0.26
0402#1 [mm] "0402 from SM-752 data"
  rect 0.8x0.6 smd: 1(-0.6,0) 2(0.6,0)
  silkscreen extent -1.22,-0.52 1.22,0.52, body extent -0.55,-0.3 0.55,0.3, height 0.6
0402#2 [mm] "0402 from SM-752 data"
  rect 0.8x0.6 smd: 1(-0.625,-0.102) 2(0.575,-0.102)
  silkscreen extent -1.22,-0.52 1.22,0.52, body extent -0.55,-0.3 0.55,0.3, height 0.6
0603 [mm] "0603 from SM-752 data"
  rect 1x0.95 smd: 1(-0.8,0) 2(0.8,0)
  silkscreen extent -1.52,-0.69 1.52,0.69, body extent -0.87,-0.47 0.87,0.47, height 1
0805_HV [mil] "0805 with 30mil clearance between pads"
  rect 50x63 smd: 1(-40,0) 2(40,0)
  silkscreen extent -74,-40 74,40, body extent -43,-29 43,29, height 57
1206_190 [mm] "1206_190"
  rect 1.1x1.6 smd: 1(-1.7,0) 2(1.7,0)
  silkscreen extent -0.9,-1 0.9,1, body extent -1.75,-0.95 1.75,0.95, height 1.9
1210 [mm] "1210 from SM-752 data"
  rect 1.3x2.7 smd: 1(-1.45,0) 2(1.45,0)
  silkscreen extent -2.32,-1.57 2.32,1.57, body extent -1.7,-1.35 1.7,1.35, height 1.35
3216-18 [mm] "Medium density IPC, based on Kemet T495 dimensions"
  rect 1.8x1.25 smd: 1(-1.3,0) 2(1.3,0)
  silkscreen extent -2.49,-0.54 -2.49,0.54, body extent -1.7,-0.9 1.7,0.9, height 1.8
3528-21 [mm] "Medium Density IPC, based on SM-782 section 8.4"
  rect 1.95x2.25 smd: 1(-1.375,0) 2(1.375,0)
  silkscreen extent -2.29,-1.5 0.76,1.5, body extent -1.85,-1.5 1.85,1.5, height 2.1
6091 [mil] "Keystone Insulated End Launch Banana Jack"
  rect 320x220 smd: 1(185,0)
  silkscreen extent 5,-120 355,120, body extent -666,-216 271,216, height 227
6092 [mil] "Keystone Insulated End Launch Banana Jack"
  rect 320x220 smd: 1(185,0)
  silkscreen extent 5,-120 355,120, body extent -666,-216 271,216, height 227
7343-31 [mm] "Medium Density based on Kemet T495 dimensions"
  rect 2.55x2.45 smd: 1(-3.025,0) 2(3.025,0)
  silkscreen extent -4.56,-2.3 3.8,2.3, body extent -3.8,-2.3 3.8,2.3, height 3.1
ACM9070 [mm] "TDK recommended land pattern 005-02/20090710/e9713_acm"
  rect 2.5x1.5 smd: 1(-4.25,1.75) 2(-4.25,-1.75) 3(4.25,-1.75) 4(4.25,1.75)
  silkscreen extent -5.85,-3.6 5.85,3.6, body extent -4.6,-3.6 4.6,3.6, height 4.5
AssemblyNote [mil] "Assembly Note"
AssemblyNoteLabel [mil] "Assembly Note for PCB Labels"
CONN_5-146261-1 [mm] "Sullins"
  rect 1.5x1.5 hole 1.02: 1(-1.27,0)
  round 1.5 hole 1.02: 2(1.27,0)
  silkscreen extent -3.68,-1.27 2.54,1.27, body extent -2.51,-1.27 2.51,1.27, height 10.87
CONN_22112042 [mm] "Molex"
  rect 1.65x1.65 hole 1.016 mask+0: 1(-3.81,0)
  round 1.65 hole 1.016 mask+0: 2(-1.27,0) 3(1.27,0) 4(3.81,0)
  silkscreen extent -5.08,-3.25 5.08,3.1, body extent -5,-3.25 5,3.1, height 10.68
CONN_PEC05DAAN [mm] "SULLINS"
  rect 1.65x1.65 hole 1.016 mask+0: 1(-5.08,-1.27)
  round 1.65 hole 1.016 mask+0: 2(-5.08,1.27) 3(-2.54,-1.27) 4(-2.54,1.27) 5(0,-1.27) 6(0,1.27) 7(2.54,-1.27) 8(2.54,1.27) 9(5.08,-1.27) 10(5.08,1.27)
  silkscreen extent -7.45,-2.6 6.35,2.54, body extent -6.35,-2.54 6.35,2.54, height 8.38
CONN_PEC07DAAN [mm] "SULLINS"
  rect 1.65x1.65 hole 1.016 mask+0: 1(-7.62,-1.27)
  round 1.65 hole 1.016 mask+0: 2(-7.62,1.27) 3(-5.08,-1.27) 4(-5.08,1.27) 5(-2.54,-1.27) 6(-2.54,1.27) 7(0,-1.27) 8(0,1.27) 9(2.54,-1.27) 10(2.54,1.27) 11(5.08,-1.27) 12(5.08,1.27) 13(7.62,-1.27) 14(7.62,1.27)
  silkscreen extent -9.99,-2.6 8.89,2.54, body extent -8.95,-2.6 8.95,2.6, height 11.43
CONN_PJ-102A [mm] "CUI INC"
  oval 1.5x2.1 hole 1 slot 1.6 at 90 deg: 1(-3,0) 2(3,0)
  oval 2.1x1.5 hole 1 slot 1.6 at 0 deg: 3(0,4.7)
  silkscreen extent -3.7,-4.5 10.7,4.9, body extent -3.7,-4.5 10.7,4.9, height 11.02
CONN_USB-Mini-B-1734035-2 [mm] "Tyco Connectivity recommended land pattern"
  rect 0.5x2.3 smd: 1(-1.6,2.6) 2(-0.8,2.6) 3(0,2.6) 4(0.8,2.6) 5(1.6,2.6)
  rect 2x2.5 smd: 6(4.45,2.5) 7(4.45,-3) 8(-4.45,-3) 9(-4.45,2.5)
  round 0.9 hole 0.9 unplated: 10(2.2,0) 11(-2.2,0)
  silkscreen extent -5,-5 4.9,4.19, body extent -4.95,-5.9 4.95,3.3, height 4.1
DRB0008A [mm] "SON, 8-Leads, Body 3x3mm, Pitch 0.65mm, Thermal Pad 1.75x1.5mm, TI Recommended"
  oval 0.6x0.3 smd: 1(-1.4,0.975) 2(-1.4,0.325) 3(-1.4,-0.325) 4(-1.4,-0.975) 5(1.4,-0.975) 6(1.4,-0.325) 7(1.4,0.325) 8(1.4,0.975)
  rect 1.5x1.75 smd paste-0.75: 9(0,0)
  Top Layer region: -0.465,-1.5 -0.465,-0.875 -0.75,-0.875 -0.75,0.875 -0.465,0.875 -0.465,1.5 -0.185,1.5 -0.185,0.875 0.185,0.875 0.185,1.5 0.465,1.5 0.465,0.875 0.75,0.875 0.75,-0.875 0.465,-0.875 0.465,-1.5 0.185,-1.5 0.185,-0.875 -0.185,-0.875 -0.185,-1.5
  silkscreen extent -1.73,-1.73 1.73,1.73, body extent -1.57,-1.57 1.58,1.58, height 1.01
DRC0010J [mm] "SON, 10-Leads, Body 3x3mm, Pitch 0.5mm, Thermal Pad 2.4x1.65mm, TI Recommended"
  rrect100% 0.6x0.24 smd: 1(-1.4,1) 2(-1.4,0.5) 3(-1.4,0) 4(-1.4,-0.5) 5(-1.4,-1) 6(1.4,-1) 7(1.4,-0.5) 8(1.4,0) 9(1.4,0.5) 10(1.4,1)
  rrect6% 1.65x2.4 smd paste-0.825: 11(0,0)
  silkscreen extent -1.7,-1.7 1.7,1.7, body extent -1.55,-1.55 1.55,1.55, height 1.01
DRL0005A [mm] "SOTFL, 5-Flat Leads, Body 1.2x1.6x0.6mm, Pitch 0.5mm, TI recommended"
  rect 0.5x0.3 smd: 1(-0.75,0.5) 2(-0.75,0) 3(-0.75,-0.5) 4(0.75,-0.5) 5(0.75,0.5)
  silkscreen extent -0.9,-0.95 0.9,0.95, body extent -0.85,-0.85 0.85,0.85, height 0.62
DRY0006A [mm] "PSON, 6-Leads, Body 1x1.45mm, Pitch 0.5mm, TI Recommended"
  rect 0.35x0.2 smd: 1(-0.275,0.5)
  rect 0.3x0.2 smd: 2(-0.3,0) 3(-0.3,-0.5) 4(0.3,-0.5) 5(0.3,0) 6(0.3,0.5)
  silkscreen extent -0.5,-0.85 0.2,0.85, body extent -0.53,-0.75 0.53,0.75, height 0.61
Emerson_142-0701-851 [mil] "Johnson Components"
  rect 45x200 smd: 1(0,-110)
  rect 95x200 smd: 2(-172.5,-110) 3(172.5,-110)
  rect 95x200 smd far side: 4(172.5,-110) 5(-172.5,-110)
  silkscreen extent -235,-220 235,0, body extent -190,-195 190,387, height 155
FCC_disclaimer [mil]
FOX_FXO-HC73 [mm] "SMD, 4-Leads, Body 7x5mm"
  rect 2x1.8 smd: 1(-2.1,2.54) 2(-2.1,-2.54) 3(2.1,-2.54) 4(2.1,2.54)
  silkscreen extent -2.6,-3.75 2.6,4, body extent -2.6,-3.75 2.6,3.75, height 1.41
FUSE_429 [mm] "SMD, 2-Leads, Body 3.18x1.52mm, Height 1.14mm"
  rect 1.14x2.03 smd: 1(-1.33,0) 2(1.33,0)
  silkscreen extent -0.37,-0.87 0.35,0.87, body extent -1.6,-0.76 1.6,0.76, height 1.14
IND_DLW21S [mm] "muRata"
  rect 0.4x0.9 smd: 1(-0.45,0.85) 2(-0.45,-0.85) 3(0.45,-0.85) 4(0.45,0.85)
  silkscreen extent -0.96,0.88 -0.92,0.92, body extent -0.7,-1.1 0.7,1.1, height 1.41
KSR [mm] "C&K Components SPST switch"
  rect 1.5x1.4 smd: 1(-3.25,0) 2(3.25,0)
  silkscreen extent -3.2,-2 3.2,2, body extent -3,-1.9 3,1.9, height 2.65
Label_1250x250 [mil] "Thermal Transfer Labels"
  round 1 on Mech13: 0(0,0)
  silkscreen extent -625,-125 625,125, body extent -625,-125 625,125, height 1
Laird_BMI-S-201-F [mm] "SMD, 8-Leads, Body 13.06x14.02mm"
  round 0.5 smd: 1(-6.25,-6.694) 1(-6.25,0) 1(-6.25,6.694) 1(0,-6.75) 1(0,6.75) 1(6.25,-6.694) 1(6.25,0) 1(6.25,6.694)
  Top Layer region: 5.75,-1.9 6.75,-1.9 6.75,1.9 5.75,1.9
  Top Layer region: 4.1,-7.23 4.1,-6.23 5.75,-6.23 5.75,-4.1 6.75,-4.1 6.75,-7.23
  Top Layer region: 4.1,6.23 4.1,7.23 6.75,7.23 6.75,4.1 5.75,4.1 5.75,6.23
  Top Layer region: -1.9,-7.23 -1.9,-6.23 1.9,-6.23 1.9,-7.23
  Top Layer region: -6.75,-7.23 -6.75,-4.1 -5.75,-4.1 -5.75,-6.23 -4.1,-6.23 -4.1,-7.23
  Top Layer region: -6.75,-1.9 -6.75,1.9 -5.75,1.9 -5.75,-1.9
  Top Layer region: -1.9,6.23 1.9,6.23 1.9,7.23 -1.9,7.23
  Top Layer region: -6.75,4.1 -5.75,4.1 -5.75,6.23 -4.1,6.23 -4.1,7.23 -6.75,7.23
  silkscreen extent -6.53,-7.01 6.53,7.01, body extent -6.65,-7.13 6.66,7.14, height 2.54
LDC08A [mm] "PSON, 8-Leads, Body 4x4mm, Pitch 0.8mm, NSC Recommended"
  rect 0.5x0.3 smd paste-0.15 mask+0.051: 1(-1.65,1.2) 2(-1.65,0.4) 3(-1.65,-0.4) 4(-1.65,-1.2) 5(1.65,-1.2) 6(1.65,-0.4) 7(1.65,0.4) 8(1.65,1.2)
  rect 2.2x3 smd paste-1.5 mask+0.051: 9(0,0)
  silkscreen extent -2.87,-2.2 2.2,2.2, body extent -2.05,-2.05 2.05,2.05, height 0.8
LED_LTST-C190 [mm] "Lite-On"
  rect 0.8x0.8 smd: 1(-0.75,0) 2(0.75,0)
  silkscreen extent -1.1,-0.8 1.8,0.8, body extent -0.85,-0.45 0.85,0.45, height 0.9
MLP2520S-S [mm] "TDK"
  rect 0.7x2 smd: 1(-1.05,0) 2(1.05,0)
  silkscreen extent -0.5,-1.15 0.5,1.15, body extent -1.32,-1.07 1.32,1.07, height 1.2
Pb-Free_Overlay_Medium [mil]
  silkscreen extent -95,-95 95,95
PN0080A_N [mm] "QFP, 80-Leads, Body 12x12mm, Pitch 0.5mm, IPC Medium Density"
  oval 1.45x0.3 smd: 1(-6.725,4.75) 2(-6.725,4.25) 3(-6.725,3.75) 4(-6.725,3.25) 5(-6.725,2.75) 6(-6.725,2.25) 7(-6.725,1.75) 8(-6.725,1.25) 9(-6.725,0.75) 10(-6.725,0.25) 11(-6.725,-0.25) 12(-6.725,-0.75) 13(-6.725,-1.25) 14(-6.725,-1.75) 15(-6.725,-2.25) 16(-6.725,-2.75) 17(-6.725,-3.25) 18(-6.725,-3.75) 19(-6.725,-4.25) 20(-6.725,-4.75) 41(6.725,-4.75) 42(6.725,-4.25) 43(6.725,-3.75) 44(6.725,-3.25) 45(6.725,-2.75) 46(6.725,-2.25) 47(6.725,-1.75) 48(6.725,-1.25) 49(6.725,-0.75) 50(6.725,-0.25) 51(6.725,0.25) 52(6.725,0.75) 53(6.725,1.25) 54(6.725,1.75) 55(6.725,2.25) 56(6.725,2.75) 57(6.725,3.25) 58(6.725,3.75) 59(6.725,4.25) 60(6.725,4.75)
  oval 0.3x1.45 smd: 21(-4.75,-6.725) 22(-4.25,-6.725) 23(-3.75,-6.725) 24(-3.25,-6.725) 25(-2.75,-6.725) 26(-2.25,-6.725) 27(-1.75,-6.725) 28(-1.25,-6.725) 29(-0.75,-6.725) 30(-0.25,-6.725) 31(0.25,-6.725) 32(0.75,-6.725) 33(1.25,-6.725) 34(1.75,-6.725) 35(2.25,-6.725) 36(2.75,-6.725) 37(3.25,-6.725) 38(3.75,-6.725) 39(4.25,-6.725) 40(4.75,-6.725) 61(4.75,6.725) 62(4.25,6.725) 63(3.75,6.725) 64(3.25,6.725) 65(2.75,6.725) 66(2.25,6.725) 67(1.75,6.725) 68(1.25,6.725) 69(0.75,6.725) 70(0.25,6.725) 71(-0.25,6.725) 72(-0.75,6.725) 73(-1.25,6.725) 74(-1.75,6.725) 75(-2.25,6.725) 76(-2.75,6.725) 77(-3.25,6.725) 78(-3.75,6.725) 79(-4.25,6.725) 80(-4.75,6.725)
  silkscreen extent -6.85,-5.6 5.6,5.6, body extent -7,-7 7,7, height 1.56
PWP0014E_N [mm] "TSOP, 14-Leads, Body 5x4.4mm, Pitch 0.65mm, Thermal Pad 3x3 mm, IPC Medium Density"
  rrect100% 1.4x0.45 smd: 1(-2.95,1.95) 2(-2.95,1.3) 3(-2.95,0.65) 4(-2.95,0) 5(-2.95,-0.65) 6(-2.95,-1.3) 7(-2.95,-1.95) 8(2.95,-1.95) 9(2.95,-1.3) 10(2.95,-0.65) 11(2.95,0) 12(2.95,0.65) 13(2.95,1.3) 14(2.95,1.95)
  rrect4% 2.46x2.36 smd: 15(0,0)
  silkscreen extent -3.5,-2.65 1.7,2.65, body extent -3.21,-2.5 3.21,2.5, height 1
PWP0028D_N [mm] "TSOP, 28-Leads, Body 9.7x4.4mm, Pitch 0.65mm, Exposed Pad, IPC Medium Density"
  rrect100% 1.4x0.45 smd: 1(-2.95,4.225) 2(-2.95,3.575) 3(-2.95,2.925) 4(-2.95,2.275) 5(-2.95,1.625) 6(-2.95,0.975) 7(-2.95,0.325) 8(-2.95,-0.325) 9(-2.95,-0.975) 10(-2.95,-1.625) 11(-2.95,-2.275) 12(-2.95,-2.925) 13(-2.95,-3.575) 14(-2.95,-4.225) 15(2.95,-4.225) 16(2.95,-3.575) 17(2.95,-2.925) 18(2.95,-2.275) 19(2.95,-1.625) 20(2.95,-0.975) 21(2.95,-0.325) 22(2.95,0.325) 23(2.95,0.975) 24(2.95,1.625) 25(2.95,2.275) 26(2.95,2.925) 27(2.95,3.575) 28(2.95,4.225)
  rrect4% 2.4x6.46 smd: 29(0,0)
  silkscreen extent -3.2,-4.9 1.7,4.9, body extent -3.21,-4.85 3.21,4.85, height 1
RHS0048A [mm] "QFN, 48-Leads, Body 7x7mm, Pitch 0.5mm, TI Recommended"
  rrect40% 0.6x0.25 smd: 1(-3.4,2.75) 2(-3.4,2.25) 3(-3.4,1.75) 4(-3.4,1.25) 5(-3.4,0.75) 6(-3.4,0.25) 7(-3.4,-0.25) 8(-3.4,-0.75) 9(-3.4,-1.25) 10(-3.4,-1.75) 11(-3.4,-2.25) 12(-3.4,-2.75) 25(3.4,-2.75) 26(3.4,-2.25) 27(3.4,-1.75) 28(3.4,-1.25) 29(3.4,-0.75) 30(3.4,-0.25) 31(3.4,0.25) 32(3.4,0.75) 33(3.4,1.25) 34(3.4,1.75) 35(3.4,2.25) 36(3.4,2.75)
  rrect40% 0.25x0.6 smd: 13(-2.75,-3.4) 14(-2.25,-3.4) 15(-1.75,-3.4) 16(-1.25,-3.4) 17(-0.75,-3.4) 18(-0.25,-3.4) 19(0.25,-3.4) 20(0.75,-3.4) 21(1.25,-3.4) 22(1.75,-3.4) 23(2.25,-3.4) 24(2.75,-3.4) 37(2.75,3.4) 38(2.25,3.4) 39(1.75,3.4) 40(1.25,3.4) 41(0.75,3.4) 42(0.25,3.4) 43(-0.25,3.4) 44(-0.75,3.4) 45(-1.25,3.4) 46(-1.75,3.4) 47(-2.25,3.4) 48(-2.75,3.4)
  rrect2% 5.1x5.1 smd paste-2.55: 49(0,0)
  silkscreen extent -3.7,-3.7 3.7,3.7, body extent -3.57,-3.57 3.57,3.57, height 0.81
Rosenberger_59S20X-40ML5-Z [mm] "Connector, RF, R/A, TH"
  rect 1.9x3.4 smd: 1(0,-2.05)
  round 2.1 hole 1.6: 2(-3,-2.65) 3(3,-2.65) 4(-3,-9.65) 5(3,-9.65)
  Top Layer region: 2.1,-12.95 3.9,-12.95 3.9,-7.35 2.1,-7.35
  Top Layer region: 2.1,-5.55 3.9,-5.55 3.9,-0.35 2.1,-0.35
  Top Layer region: -3.9,-12.95 -2.1,-12.95 -2.1,-7.35 -3.9,-7.35
  Top Layer region: -3.9,-5.55 -2.1,-5.55 -2.1,-0.35 -3.9,-0.35
  silkscreen extent -3.75,-11.45 3.75,-4.18, body extent -4.25,-11.45 4.25,11.2, height 6.6
Rosenberger_D4S20L-40MA5_NoTopLayerPads [mm] "Rosenberger"
  round 1.4 hole 0.9: 1(-1,7.307) 2(-1,5.307) 3(1,5.307) 4(1,7.307)
  round 2.2 hole 1.7: MH(-3.75,10.157) MH(-3.75,2.457) MH(3.75,10.157) MH(3.75,2.457)
  silkscreen extent -4.5,0.2 4.5,11.51, body extent -6,-15.79 6,11.51, height 10.95
Samtec_TSW-128-07-G-D [mm] "Header, 2.54 mm, 28x2, TH"
  rect 1.55x1.55 hole 1.02: 1(-34.29,-1.27)
  round 1.55 hole 1.02: 2(-34.29,1.27) 3(-31.75,-1.27) 4(-31.75,1.27) 5(-29.21,-1.27) 6(-29.21,1.27) 7(-26.67,-1.27) 8(-26.67,1.27) 9(-24.13,-1.27) 10(-24.13,1.27) 11(-21.59,-1.27) 12(-21.59,1.27) 13(-19.05,-1.27) 14(-19.05,1.27) 15(-16.51,-1.27) 16(-16.51,1.27) 17(-13.97,-1.27) 18(-13.97,1.27) 19(-11.43,-1.27) 20(-11.43,1.27) 21(-8.89,-1.27) 22(-8.89,1.27) 23(-6.35,-1.27) 24(-6.35,1.27) 25(-3.81,-1.27) 26(-3.81,1.27) 27(-1.27,-1.27) 28(-1.27,1.27) 29(1.27,-1.27) 30(1.27,1.27) 31(3.81,-1.27) 32(3.81,1.27) 33(6.35,-1.27) 34(6.35,1.27) 35(8.89,-1.27) 36(8.89,1.27) 37(11.43,-1.27) 38(11.43,1.27) 39(13.97,-1.27) 40(13.97,1.27) 41(16.51,-1.27) 42(16.51,1.27) 43(19.05,-1.27) 44(19.05,1.27) 45(21.59,-1.27) 46(21.59,1.27) 47(24.13,-1.27) 48(24.13,1.27) 49(26.67,-1.27) 50(26.67,1.27) 51(29.21,-1.27) 52(29.21,1.27) 53(31.75,-1.27) 54(31.75,1.27) 55(34.29,-1.27) 56(34.29,1.27)
  silkscreen extent -36.1,-2.54 35.56,2.54, body extent -35.56,-2.54 35.56,2.54, height 8.39
SMB [mil] "Molded Diode, 2-Leads, Body 5.4x3.6mm, IPC Medium Density, based on OnSemi component dimensions"
  rect 85x107.99 smd: 1(-87.01,0) 2(87.01,0)
  silkscreen extent -155,-82 125,82, body extent -106,-71 106,71, height 91
SNT-100-BK-G [mil] "Samtec STEP model"
  round 1 on Mech3: 0(0,0)
  body extent -100,-50 100,50, height 344
SOD-123 [mm] "On Semi recommended land pattern"
  rect 0.915x1.22 smd: 1(-1.637,0) 2(1.637,0)
  silkscreen extent -2.74,-1.17 2.03,1.17, body extent -1.93,-0.9 1.93,0.9, height 1.35
SOT-23 [mm] "SOT23, 3-Leads, Body 2.9x1.3mm, Pitch 0.95mm, Lead Span 2.5mm, IPC Medium Density"
  rrect50% 1x0.6 smd: 1(-1.2,0.95) 2(-1.2,-0.95) 3(1.2,0)
  silkscreen extent -1.63,-1.5 0.7,1.5, body extent -1.16,-1.45 1.21,1.45, height 1
SULLINS_PEC10DAAN [mm] "SULLINS"
  rect 1.65x1.65 hole 1.016: 1(-1.27,11.43)
  round 1.65 hole 1.016: 2(1.27,11.43) 3(-1.27,8.89) 4(1.27,8.89) 5(-1.27,6.35) 6(1.27,6.35) 7(-1.27,3.81) 8(1.27,3.81) 9(-1.27,1.27) 10(1.27,1.27) 11(-1.27,-1.27) 12(1.27,-1.27) 13(-1.27,-3.81) 14(1.27,-3.81) 15(-1.27,-6.35) 16(1.27,-6.35) 17(-1.27,-8.89) 18(1.27,-8.89) 19(-1.27,-11.43) 20(1.27,-11.43)
  silkscreen extent -3.11,-12.96 2.79,13.25, body extent -2.79,-12.96 2.79,12.96, height 9.08
SW_218-2LP [mm] "SMD, 4-Leads, Body 3.71x5.8mm, Pitch 1.27mm"
  rect 1.27x0.76 smd: 1(-3.81,0.635) 2(-3.81,-0.635) 3(3.81,-0.635) 4(3.81,0.635)
  silkscreen extent -2.9,-1.86 2.9,2.09, body extent -4.22,-1.86 4.22,1.85, height 2.62
SW_219-8MST [mm] "SW, Tape Seal, 8POS, SMD"
  rect 2.44x1.12 smd: 1(-4.3,8.89) 2(-4.3,6.35) 3(-4.3,3.81) 4(-4.3,1.27) 5(-4.3,-1.27) 6(-4.3,-3.81) 7(-4.3,-6.35) 8(-4.3,-8.89) 9(4.3,-8.89) 10(4.3,-6.35) 11(4.3,-3.81) 12(4.3,-1.27) 13(4.3,1.27) 14(4.3,3.81) 15(4.3,6.35) 16(4.3,8.89)
  silkscreen extent -2.54,-10.89 2.54,10.89, body extent -4.95,-10.89 4.95,10.9, height 4.32
TESTPOINT [mm]
  round 8 hole 3.2: 1(0,0)
TI_Stacked_Overlay_Small [mil]
  silkscreen extent -418,-98 418,98
TSW-103-07-G-D [mm] "Samtec 100mil, 2x3, 230 mil above insulator"
  rect 1.65x1.65 hole 1.016: 1(-2.54,-1.27)
  round 1.65 hole 1.016: 2(-2.54,1.27) 3(0,-1.27) 4(0,1.27) 5(2.54,-1.27) 6(2.54,1.27)
  silkscreen extent -4.84,-2.54 3.81,2.54, body extent -3.81,-2.54 3.81,2.54, height 8.38
TSW-103-07-G-S [mm] "Samtec 100mil, 1x3, 230 mil above insulator"
  rect 1.65x1.65 hole 1.016: 1(-2.54,0)
  round 1.65 hole 1.016: 2(0,0) 3(2.54,0)
  silkscreen extent -4.83,-1.27 3.81,1.27, body extent -3.81,-1.27 3.81,1.27, height 8.38
TSW-104-07-G-D [mm] "Samtec 100mil, 2x4, 230 mil above insulator"
  rect 1.65x1.65 hole 1.016 mask+0: 1(-3.81,-1.27)
  round 1.65 hole 1.016 mask+0: 2(-3.81,1.27) 3(-1.27,-1.27) 4(-1.27,1.27) 5(1.27,-1.27) 6(1.27,1.27) 7(3.81,-1.27) 8(3.81,1.27)
  silkscreen extent -6.1,-2.54 5.08,2.54, body extent -5.08,-2.54 5.08,2.54, height 8.38
VLF302510MT [mm] "TDK"
  rect 0.9x1.45 smd: 1(-0.85,0) 2(0.85,0)
  silkscreen extent -1.45,-1.68 1.45,1.68, body extent -1.35,-1.6 1.35,1.6, height 1
WE-TPC-XLH2 [mm] "Wurth Elektronik recommended land pattern, 2008-04-11"
  rect 1.8x4.6 smd: 1(-4.5,0) 2(4.5,0)
  silkscreen extent -5.15,-5.15 5.15,5.15, body extent -5.15,-5.15 5.15,5.15, height 3.1
WL-SMCW_GREEN [mm] "WURTH"
  rect 0.8x0.8 smd: 1(-0.8,0) 2(0.8,0)
  silkscreen extent -1.9,-0.8 1.2,0.8, body extent -0.85,-0.45 0.85,0.45, height 0.8
XTAL_CSM-7X [mm] "ECS"
  rect 5.5x2 smd: 1(-4.75,0) 2(4.75,0)
  silkscreen extent -6.2,-2.5 6.2,2.5, body extent -5.95,-2.4 5.95,2.4, height 4.3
